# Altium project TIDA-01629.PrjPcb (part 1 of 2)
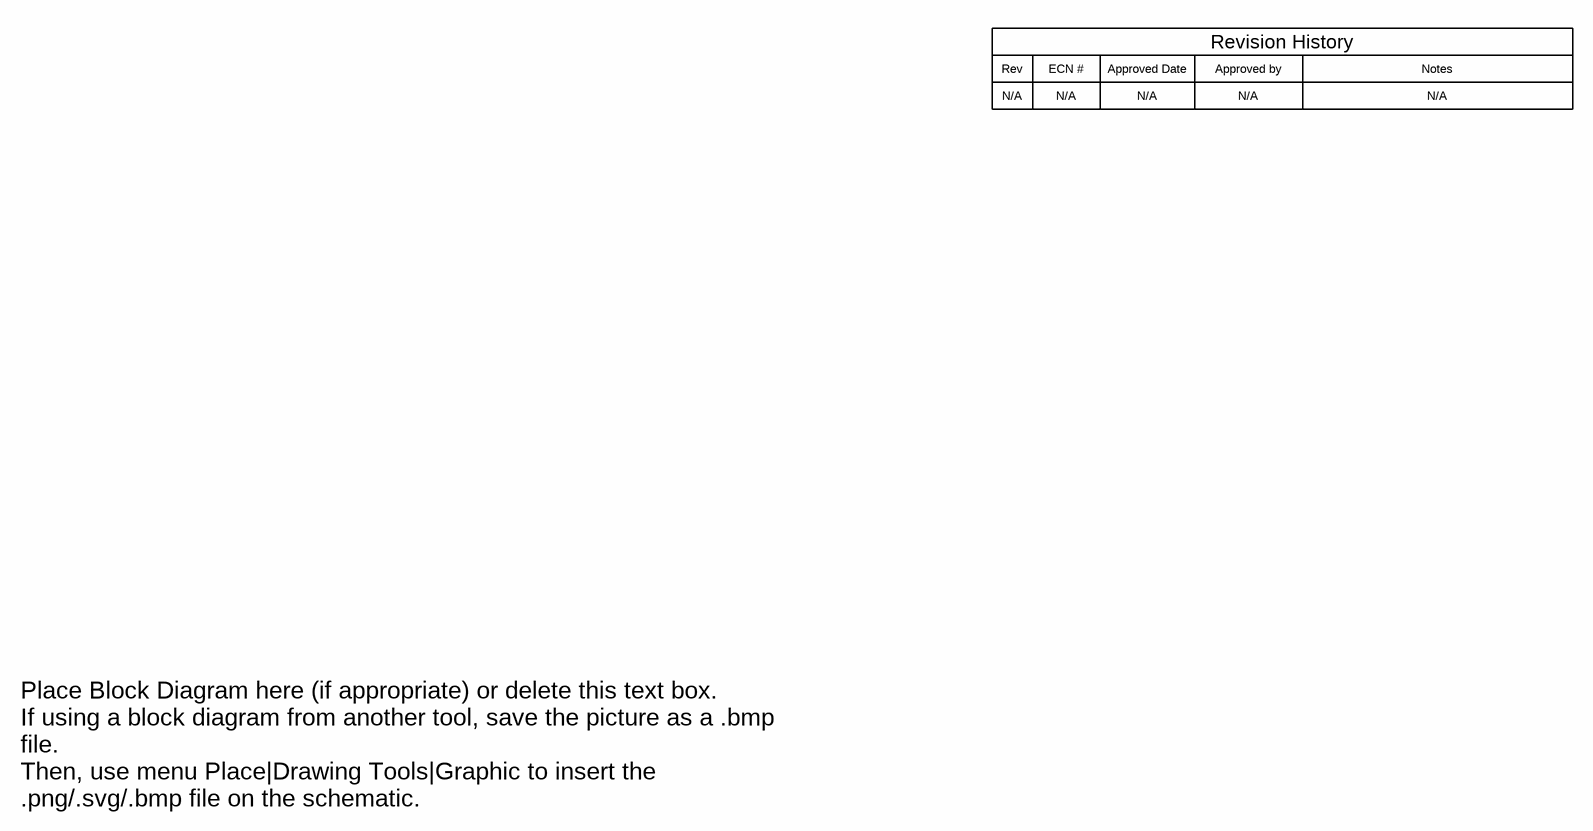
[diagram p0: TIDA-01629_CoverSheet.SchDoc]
TID: TIDA-01629; TechSupport: http://www.ti.com/support; SCH_Rev: E1; PRJ_Title: 48V/530W three phase inverter with smart gate driver; PRJ_Number: TIDA-01629; PRJ_Engineer: Kristen Mogensen; PRJ_Customer: Public Release; PCB_Rev: E1; PCB_Layout: Kristen Mogensen; ChangeMe!: N/A; CopyrightYear: 2018
6 sheets, 224 parts. Net scope: global (net labels, ports and power ports of the same name join across sheets).
Board file: TIDA-01629_PCB.PcbDoc
Sheets:
  TIDA-01629_CoverSheet.SchDoc
  TIDA-01629_CurrentSense.SchDoc
  TIDA-01629_EVM_Hardware.SchDoc
  TIDA-01629_Gate_Driver.SchDoc
  TIDA-01629_Interface.SchDoc
  TIDA-01629_Encoder.SchDoc

## Sheet TIDA-01629_CoverSheet.SchDoc
size 431 x 279 mm; Date: Not shown in title block; ApprovedBy: Not shown in title block; CheckedBy: Not shown in title block; Author: Not shown in title block; CompanyName: Not shown in title block; Engineer: Not shown in title block; Organization: Not shown in title block; Address1: Not shown in title block; Address2: Not shown in title block; Address3: Not shown in title block; Address4: Not shown in title block; DocumentNumber: 1; Revision: Use project parameter SCH_Rev; SheetNumber: 1; SheetTotal: 3; PageSetup: Record=PageOptions¦CenterHorizontal=True¦CenterVertical=True¦PrintScale=1.00¦XCorrection=1.00¦YCorrection=1.00¦PrintKind=0¦BorderSize=5000000¦LeftOffset=0¦BottomOffset=0¦Orientation=2¦PaperLength=1000¦PaperWidth=1000¦Scale=100¦PaperSource=15¦PrintQuality=600¦MediaType=1¦DitherType=10¦PaperKind=Letter¦PrintScaleMode=1

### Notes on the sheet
- Rev
- N/A
- ECN #
- Approved Date
- Approved by
- Revision History
- Notes
- Place Block Diagram here (if appropriate) or delete this text box.
  If using a block diagram from another tool, save the picture as a .bmp file.
  Then, use menu Place|Drawing Tools|Graphic to insert the .png/.svg/.bmp file on the schematic.

## Sheet TIDA-01629_CurrentSense.SchDoc
size 431 x 279 mm; Date: Not shown in title block; ApprovedBy: Not shown in title block; CheckedBy: Not shown in title block; Author: Not shown in title block; CompanyName: Not shown in title block; Engineer: Not shown in title block; Organization: Not shown in title block; Address1: Not shown in title block; Address2: Not shown in title block; Address3: Not shown in title block; Address4: Not shown in title block; DocumentNumber: 1; Revision: Use project parameter SCH_Rev; SheetNumber: 2; SheetTotal: 3; PageSetup: Record=PageOptions¦CenterHorizontal=True¦CenterVertical=True¦PrintScale=1.00¦XCorrection=1.00¦YCorrection=1.00¦PrintKind=0¦BorderSize=5000000¦LeftOffset=0¦BottomOffset=0¦Orientation=2¦PaperLength=1000¦PaperWidth=1000¦Scale=100¦PaperSource=15¦PrintQuality=600¦MediaType=1¦DitherType=10¦PaperKind=Letter¦PrintScaleMode=1
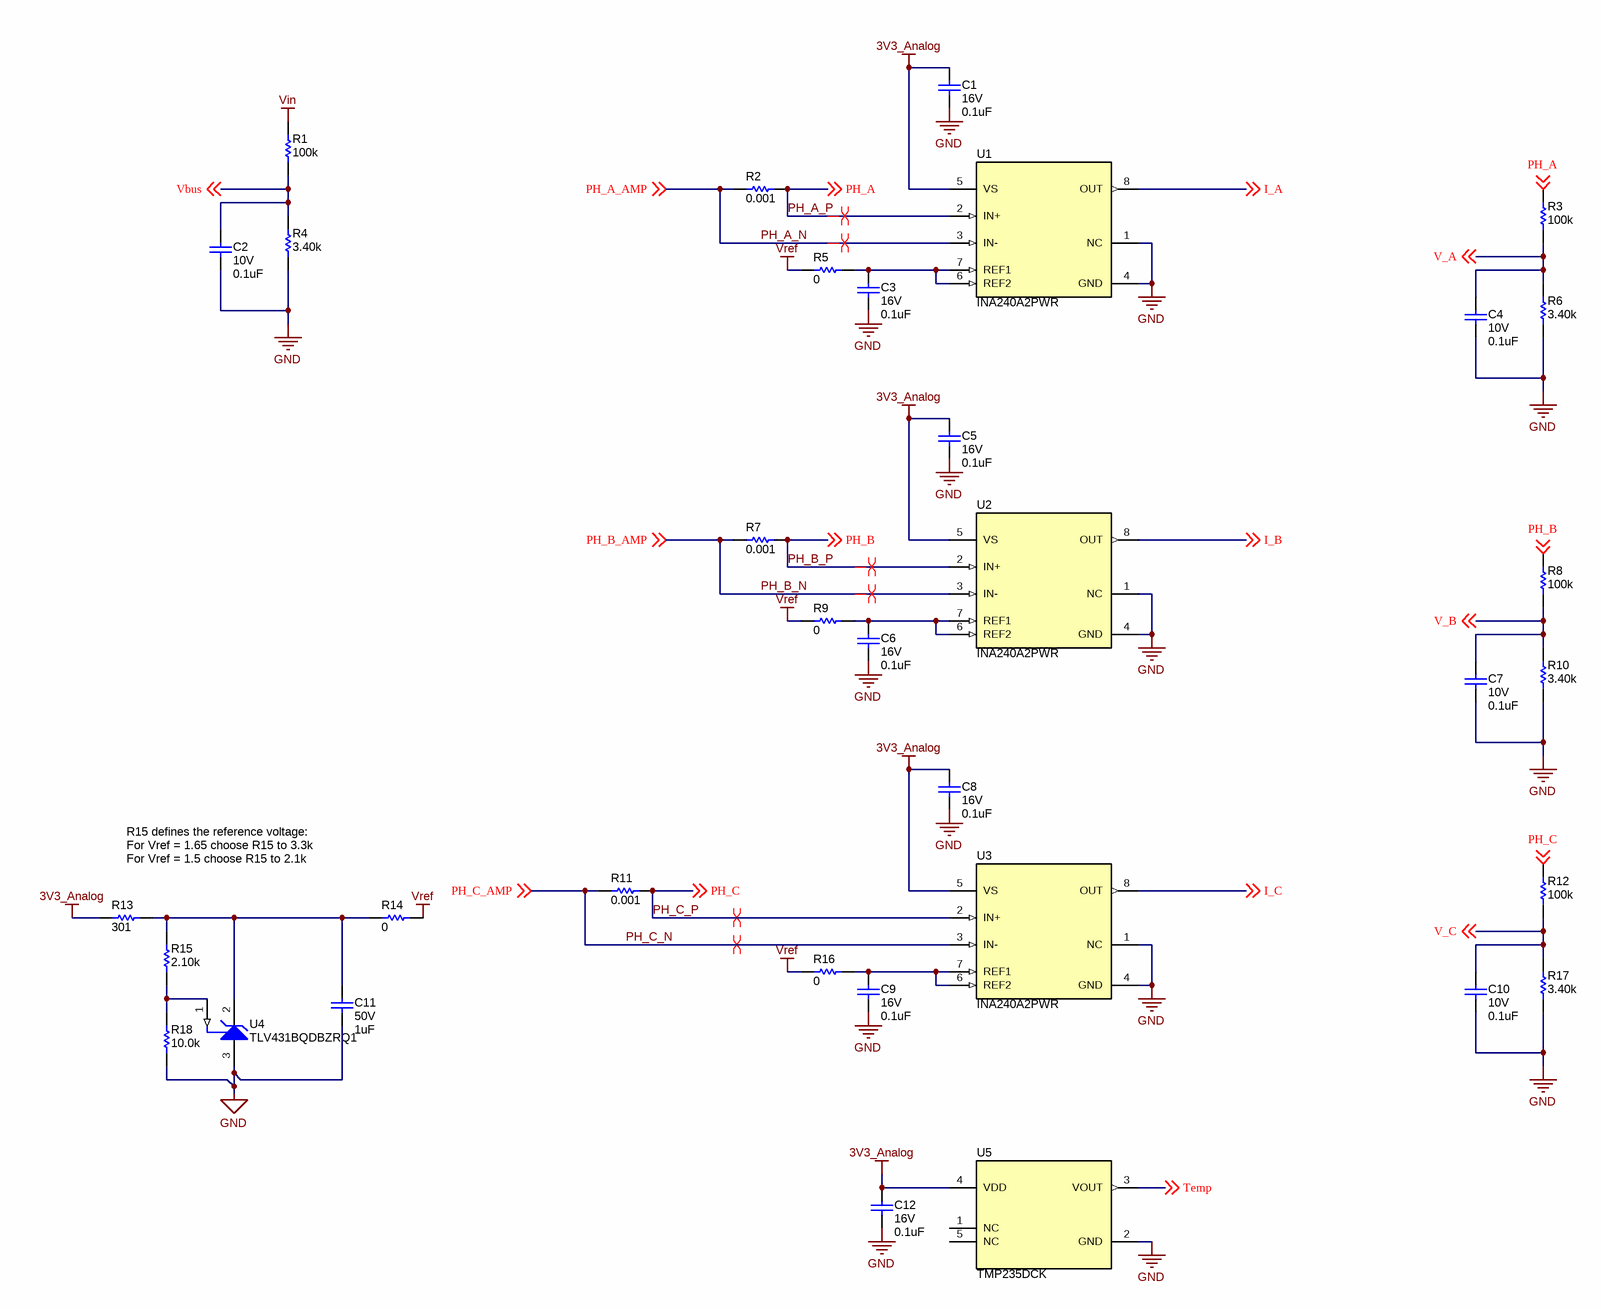
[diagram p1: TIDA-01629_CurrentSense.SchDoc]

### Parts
C1  VDC_V: 16V  ValueDisplayed: 0.1uF  [0402]  (hidden comment: 885012205037)
C2  VDC_V: 10V  ValueDisplayed: 0.1uF  [0402]  (hidden comment: GRM155R71A104KA01D)
C3  VDC_V: 16V  ValueDisplayed: 0.1uF  [0402]  (hidden comment: 885012205037)
C4  VDC_V: 10V  ValueDisplayed: 0.1uF  [0402]  (hidden comment: GRM155R71A104KA01D)
C5  VDC_V: 16V  ValueDisplayed: 0.1uF  [0402]  (hidden comment: 885012205037)
C6  VDC_V: 16V  ValueDisplayed: 0.1uF  [0402]  (hidden comment: 885012205037)
C7  VDC_V: 10V  ValueDisplayed: 0.1uF  [0402]  (hidden comment: GRM155R71A104KA01D)
C8  VDC_V: 16V  ValueDisplayed: 0.1uF  [0402]  (hidden comment: 885012205037)
C9  VDC_V: 16V  ValueDisplayed: 0.1uF  [0402]  (hidden comment: 885012205037)
C10  VDC_V: 10V  ValueDisplayed: 0.1uF  [0402]  (hidden comment: GRM155R71A104KA01D)
C11  VDC_V: 50V  ValueDisplayed: 1uF  [0805_HV]  (hidden comment: 885012207103)
C12  VDC_V: 16V  ValueDisplayed: 0.1uF  [0402]  (hidden comment: 885012205037)
R1  ValueDisplayed: 100k  [0402]  (hidden comment: CRCW0402100KFKED)
R2  ValueDisplayed: 0.001  [1206]  (hidden comment: CRF1206-FZ-R001ELF)
R3  ValueDisplayed: 100k  [0402]  (hidden comment: CRCW0402100KFKED)
R4  ValueDisplayed: 3.40k  [0402]  (hidden comment: CRCW04023K40FKED)
R5  ValueDisplayed: 0  [0402]  (hidden comment: CRCW04020000Z0ED)
R6  ValueDisplayed: 3.40k  [0402]  (hidden comment: CRCW04023K40FKED)
R7  ValueDisplayed: 0.001  [1206]  (hidden comment: CRF1206-FZ-R001ELF)
R8  ValueDisplayed: 100k  [0402]  (hidden comment: CRCW0402100KFKED)
R9  ValueDisplayed: 0  [0402]  (hidden comment: CRCW04020000Z0ED)
R10  ValueDisplayed: 3.40k  [0402]  (hidden comment: CRCW04023K40FKED)
R11  ValueDisplayed: 0.001  [1206]  (hidden comment: CRF1206-FZ-R001ELF)
R12  ValueDisplayed: 100k  [0402]  (hidden comment: CRCW0402100KFKED)
R13  ValueDisplayed: 301  [0603]  (hidden comment: CRCW0603301RFKEA)
R14  ValueDisplayed: 0  [0402]  (hidden comment: CRCW04020000Z0ED)
R15  ValueDisplayed: 2.10k  [0603]  (hidden comment: CRCW06032K10FKEA)
R16  ValueDisplayed: 0  [0402]  (hidden comment: CRCW04020000Z0ED)
R17  ValueDisplayed: 3.40k  [0402]  (hidden comment: CRCW04023K40FKED)
R18  ValueDisplayed: 10.0k  [0402]  (hidden comment: CRCW040210K0FKED)
U1  INA240A2PWR  [PW0008A_L]
U2  INA240A2PWR  [PW0008A_L]
U3  INA240A2PWR  [PW0008A_L]
U4  TLV431BQDBZRQ1  [DBZ0003A_N]
U5  TMP235DCK  [DCK0005A_N]

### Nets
3V3_Analog: C1.1 C5.1 C8.1 C12.1 R13.1 U1.5(VS) U2.5(VS) U3.5(VS) U5.4(VDD)
GND: C1.2 C2.2 C3.2 C4.2 C5.2 C6.2 C7.2 C8.2 C9.2 C10.2 C11.2 C12.2 R4.1 R6.1 R10.1 R17.1 R18.1 U1.1(NC) U1.4(GND) U2.1(NC) U2.4(GND) U3.1(NC) U3.4(GND) U4.3(ANODE) U5.2(GND)
Vin: R1.1
Vref: R5.2 R9.2 R14.1 R16.2
I_A: U1.8(OUT) ; off-sheet I_A
I_B: U2.8(OUT) ; off-sheet I_B
I_C: U3.8(OUT) ; off-sheet I_C
PH_A_N: R2.1 U1.3(IN-) ; off-sheet PH_A_AMP  [also labelled PH_A_AMP]
PH_A_P: R2.2 R3.1 U1.2(IN+) ; off-sheet PH_A  [also labelled PH_A]
PH_B_N: R7.1 U2.3(IN-) ; off-sheet PH_B_AMP  [also labelled PH_B_AMP]
PH_B_P: R7.2 R8.1 U2.2(IN+) ; off-sheet PH_B  [also labelled PH_B]
PH_C_N: R11.1 U3.3(IN-) ; off-sheet PH_C_AMP  [also labelled PH_C_AMP]
PH_C_P: R11.2 R12.1 U3.2(IN+) ; off-sheet PH_C  [also labelled PH_C]
Temp: U5.3(VOUT) ; off-sheet Temp
V_A: C4.1 R3.2 R6.2 ; off-sheet V_A
V_B: C7.1 R8.2 R10.2 ; off-sheet V_B
V_C: C10.1 R12.2 R17.2 ; off-sheet V_C
Vbus: C2.1 R1.2 R4.2 ; off-sheet Vbus
NetC3_1: C3.1 R5.1 U1.6(REF2) U1.7(REF1)
NetC6_1: C6.1 R9.1 U2.6(REF2) U2.7(REF1)
NetC9_1: C9.1 R16.1 U3.6(REF2) U3.7(REF1)
NetC11_1: C11.1 R13.2 R14.2 R15.2 U4.2(CATHODE)
NetR15_1: R15.1 R18.2 U4.1(REF)

Not connected (* = marked no-connect by the designer): U5 1(NC) 5(NC)

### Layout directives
differential pair: PH_A_N, PH_A_P, PH_B_N, PH_B_P, PH_C_N, PH_C_P

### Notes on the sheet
- R15 defines the reference voltage:
  For Vref = 1.65 choose R15 to 3.3k
  For Vref = 1.5 choose R15 to 2.1k

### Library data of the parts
C1 C3 C5 C6 C8 C9 C12 = CMP-0006228-2: CAP, CERM, 0.1 uF, 16 V, +/- 10%, X7R, 0402; Manufacturer: Wurth Elektronik; TaMin_C: -55°C; Polarized: N; SizeAreaWB_mm2: 3; Value1: Unknown; U/M: EA; Value: 0.1uF; TaMax_C: 125°C; SizeZ_mm: 0.6; SizeX_mm: 1; SizeY_mm: 0.5; Cap_F: 100nF; AEC Category: Q200
C2 C4 C7 C10 = CMP-0006629-2: CAP, CERM, 0.1 uF, 10 V, +/- 10%, X7R, 0402; Manufacturer: MuRata; TaMin_C: -55°C; Polarized: N; SizeAreaWB_mm2: 3; Value1: Unknown; U/M: EA; Value: 0.1uF; TaMax_C: 125°C; SizeZ_mm: 0.6; SizeX_mm: 1; SizeY_mm: 0.5; Cap_F: 100nF; AEC Category: Q200
C11 = CMP-0007696-2: CAP, CERM, 1 uF, 50 V, +/- 10%, X7R, 0805; Manufacturer: Wurth Elektronik; TaMin_C: -55°C; Polarized: N; SizeAreaWB_mm2: 6.75; Value1: Unknown; U/M: EA; Value: 1uF; TaMax_C: 125°C; SizeZ_mm: 1.45; SizeX_mm: 2; SizeY_mm: 1.25; Cap_Case: 0805; SizeArea_mm2: 2.5; Cap_F: 1µF; AEC Category: Q200
R1 R3 R8 R12 = CMP-0025950-3: RES, 100 k, 1%, 0.063 W, AEC-Q200 Grade 0, 0402; Manufacturer: Vishay-Dale; Power_W: 63mW; TempCo: 100 ppm/C; Value: 100k; EIA_Code: E96; SizeX_mm: 1; SizeY_mm: 0.5; SizeZ_mm: 0.6; Value2: 0.063W; AEC Qualified: Y; VDC_V: 50V; AEC Category: Q200; AEC Grade: 0
R2 R7 R11 = CMP-0078821-1: RES, 0.001, 1%, 1 W, AEC-Q200 Grade 0, 1206; Manufacturer: Bourns; Value_Code: 1L000; SizeArea_mm2: 5.12; AEC Qualified: Y; AEC Category: Q200; Res_ohm: 1m; Value: 0.001; SizeZ_mm: 1.35; EIA_Code: E96; TempCo: 50 ppm/C; AEC Grade: 0; SizeY_mm: 1.6; Power_W: 1W; SizeX_mm: 3.2
R4 R6 R10 R17 = CMP-0026334-2: RES, 3.40 k, 1%, 0.063 W, AEC-Q200 Grade 0, 0402; Manufacturer: Vishay-Dale; Power_W: 63mW; TempCo: 100 ppm/C; Value_Code: 3k40; Value: 3.40k; EIA_Code: E96; Res_ohm: 3.4k; SizeX_mm: 1; SizeY_mm: 0.5; SizeZ_mm: 0.6; Value2: 0.063W; AEC Qualified: Y; VDC_V: 50V; AEC Category: Q200; AEC Grade: 0
R5 R9 R14 R16 = CMP-0026822-2: RES, 0, 5%, 0.063 W, 0402; Manufacturer: Vishay-Dale; Power_W: 63mW; TempCo: 200 ppm/C; Value_Code: 0000; U/M: EA; Value: 0; EIA_Code: E24; SizeX_mm: 1; SizeY_mm: 0.5; SizeZ_mm: 0.6; Value2: 0.063W; VDC_V: 50V; AEC Category: Q200
R13 = CMP-0022321-5: RES, 301, 1%, 0.1 W, AEC-Q200 Grade 0, 0603; Manufacturer: Vishay-Dale; Power_W: 100mW; TempCo: 100 ppm/C; Value_Code: 301R; Value: 301; EIA_Code: E96; SizeX_mm: 1.6; SizeY_mm: 0.8; SizeZ_mm: 1; Value2: 0.1W; SizeArea_mm2: 1.28; AEC Qualified: Y; VDC_V: 75V; AEC Category: Q200; AEC Grade: 0
R15 = CMP-0022270-4: RES, 2.10 k, 1%, 0.1 W, AEC-Q200 Grade 0, 0603; Manufacturer: Vishay-Dale; Power_W: 100mW; TempCo: 100 ppm/C; Value_Code: 2k10; Value: 2.10k; EIA_Code: E96; Res_ohm: 2.1k; SizeX_mm: 1.6; SizeY_mm: 0.8; SizeZ_mm: 1; Value2: 0.1W; SizeArea_mm2: 1.28; AEC Qualified: Y; VDC_V: 75V; AEC Category: Q200; AEC Grade: 0
R18 = CMP-0025958-3: RES, 10.0 k, 1%, 0.063 W, AEC-Q200 Grade 0, 0402; Manufacturer: Vishay-Dale; Power_W: 63mW; TempCo: 100 ppm/C; Value_Code: 10k0; Value: 10.0k; EIA_Code: E96; Res_ohm: 10k; SizeX_mm: 1; SizeY_mm: 0.5; SizeZ_mm: 0.6; Value2: 0.063W; AEC Qualified: Y; VDC_V: 50V; AEC Category: Q200; AEC Grade: 0
U1-U3 = CMP-0075735-1: High/Low Side, Bi-Directional Zero-Drift Current Sense Amp w/ Enhanced PWM Rejection, PW0008A (TSSOP-8); Alternate Manufacturer: Texas Instruments; SizeX_mm: 6.4; CompType: IC; SizeAreaWB_mm2: 42.0; SizeZ_mm: 1.2; SizeY_mm: 3.0; U/M: EA; SizeArea_mm2: 19.2
U4 = CMP-0033032-1: Automotive Catalog Low-Voltage Adjustable Precision Shunt Regulator, 15 mA, -40 to 125 degC, 3-pin SOT-23 (DBZ), Green (RoHS & no Sb/Br); Manufacturer: Texas Instruments; VO Adj(Min)(V): 1.24; Iout/Iz(Max)(mA): 15; Min Iz for Regulation(uA): 80; Initial Accuracy @ 25/deg C(%): 0.5; VO Adj(Max)(V): 6; SubFamily: Shunt Voltage Reference
U5 = CMP-0013250-2: TMP235DCK, DCK0005A (SOT-5); Manufacturer: Texas Instruments; SizeX_mm: 2.1; SizeY_mm: 2; CompType: IC; SizeZ_mm: 1.1; SizeArea_mm2: 4.2; SizeAreaWB_mm2: 9.3; U/M: EA

## Sheet TIDA-01629_EVM_Hardware.SchDoc
size 431 x 279 mm; Date: Not shown in title block; ApprovedBy: Not shown in title block; CheckedBy: Not shown in title block; Author: Not shown in title block; CompanyName: Not shown in title block; Engineer: Not shown in title block; Organization: Not shown in title block; Address1: Not shown in title block; Address2: Not shown in title block; Address3: Not shown in title block; Address4: Not shown in title block; DocumentNumber: 1; Revision: Use project parameter SCH_Rev; SheetNumber: 3; SheetTotal: 3; PageSetup: Record=PageOptions¦CenterHorizontal=True¦CenterVertical=True¦PrintScale=1.00¦XCorrection=1.00¦YCorrection=1.00¦PrintKind=0¦BorderSize=5000000¦LeftOffset=0¦BottomOffset=0¦Orientation=2¦PaperLength=1000¦PaperWidth=1000¦Scale=100¦PaperSource=15¦PrintQuality=600¦MediaType=1¦DitherType=10¦PaperKind=Letter¦PrintScaleMode=1
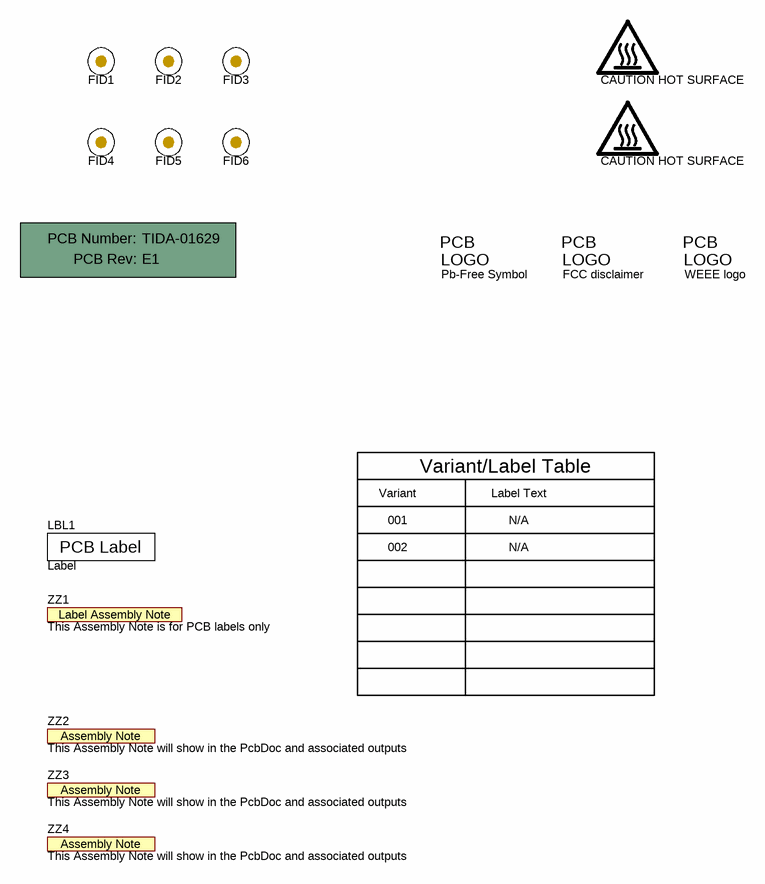
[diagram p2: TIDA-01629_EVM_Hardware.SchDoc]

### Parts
!PCB1  Printed Circuit Board  (value not drawn)  (mechanical)
FID1  Fiducial  [Fiducial10-20]  (value not drawn)
FID2  Fiducial  [Fiducial10-20]  (value not drawn)
FID3  Fiducial  [Fiducial10-20]  (value not drawn)
FID4  Fiducial  [Fiducial10-20]  (value not drawn)
FID5  Fiducial  [Fiducial10-20]  (value not drawn)
FID6  Fiducial  [Fiducial10-20]  (value not drawn)
LBL1  Label  [Label_650x200]
LOGO1  CAUTION HOT SURFACE  [IEC_HotSurface_Small]  (no BOM)
LOGO2  CAUTION HOT SURFACE  [IEC_HotSurface_Small]  (no BOM)
Logo4  Pb-Free Symbol  [Pb-Free_Overlay_Small]  (no BOM)
Logo5  FCC disclaimer  [FCC_disclaimer]  (no BOM)
Logo6  WEEE logo  [WEEE_Minimum]  (no BOM)
ZZ1  This Assembly Note is for PCB labels only  [AssemblyNoteLabel]  (no BOM)
ZZ2  This Assembly Note will show in the PcbDoc and associated outputs  [AssemblyNote]  (no BOM)
ZZ3  This Assembly Note will show in the PcbDoc and associated outputs  [AssemblyNote]  (no BOM)
ZZ4  This Assembly Note will show in the PcbDoc and associated outputs  [AssemblyNote]  (no BOM)

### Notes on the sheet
- Variant
- Variant/Label Table
- Label Text
- 001
- 002
- N/A

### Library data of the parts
!PCB1 = CMP-0003618-2: Manufacturer: Any; PartNumber: TIDA-01629
FID1-FID6 = CMP-0077181-1: Fiducial mark.  There is nothing to buy or mount.
LBL1 = CMP-0003625-1: Thermal Transfer Printable Labels, 0.650" W x 0.200" H - 10,000 per roll; Manufacturer: Brady; PartNumber: THT-14-423-10; Note: Size: 0.65" x 0.20 "
LOGO1 LOGO2 = CMP-0074837-1: IEC 61010-1 Hot Surface Warning; SymbolCreator: a0412235
Logo4 = CMP-0074839-1: SymbolCreator: a0412235; Library Reference: Logo
Logo5 = CMP-0074847-1: FCC_disclaimer; Library Reference: Logo
Logo6 = CMP-0074769-1
ZZ1 = CMP-0003616-3
ZZ2-ZZ4 = AssemblyNote: SymbolCreator: codlsc

## Sheet TIDA-01629_Gate_Driver.SchDoc
size 431 x 279 mm; Date: Not shown in title block; ApprovedBy: Not shown in title block; CheckedBy: Not shown in title block; Author: Not shown in title block; CompanyName: Not shown in title block; Engineer: Not shown in title block; Organization: Not shown in title block; Address1: Not shown in title block; Address2: Not shown in title block; Address3: Not shown in title block; Address4: Not shown in title block; DocumentNumber: 1; Revision: Use project parameter SCH_Rev; SheetNumber: 2; SheetTotal: 3; PageSetup: Record=PageOptions¦CenterHorizontal=True¦CenterVertical=True¦PrintScale=1.00¦XCorrection=1.00¦YCorrection=1.00¦PrintKind=0¦BorderSize=5000000¦LeftOffset=0¦BottomOffset=0¦Orientation=2¦PaperLength=1000¦PaperWidth=1000¦Scale=100¦PaperSource=15¦PrintQuality=600¦MediaType=1¦DitherType=10¦PaperKind=Letter¦PrintScaleMode=1
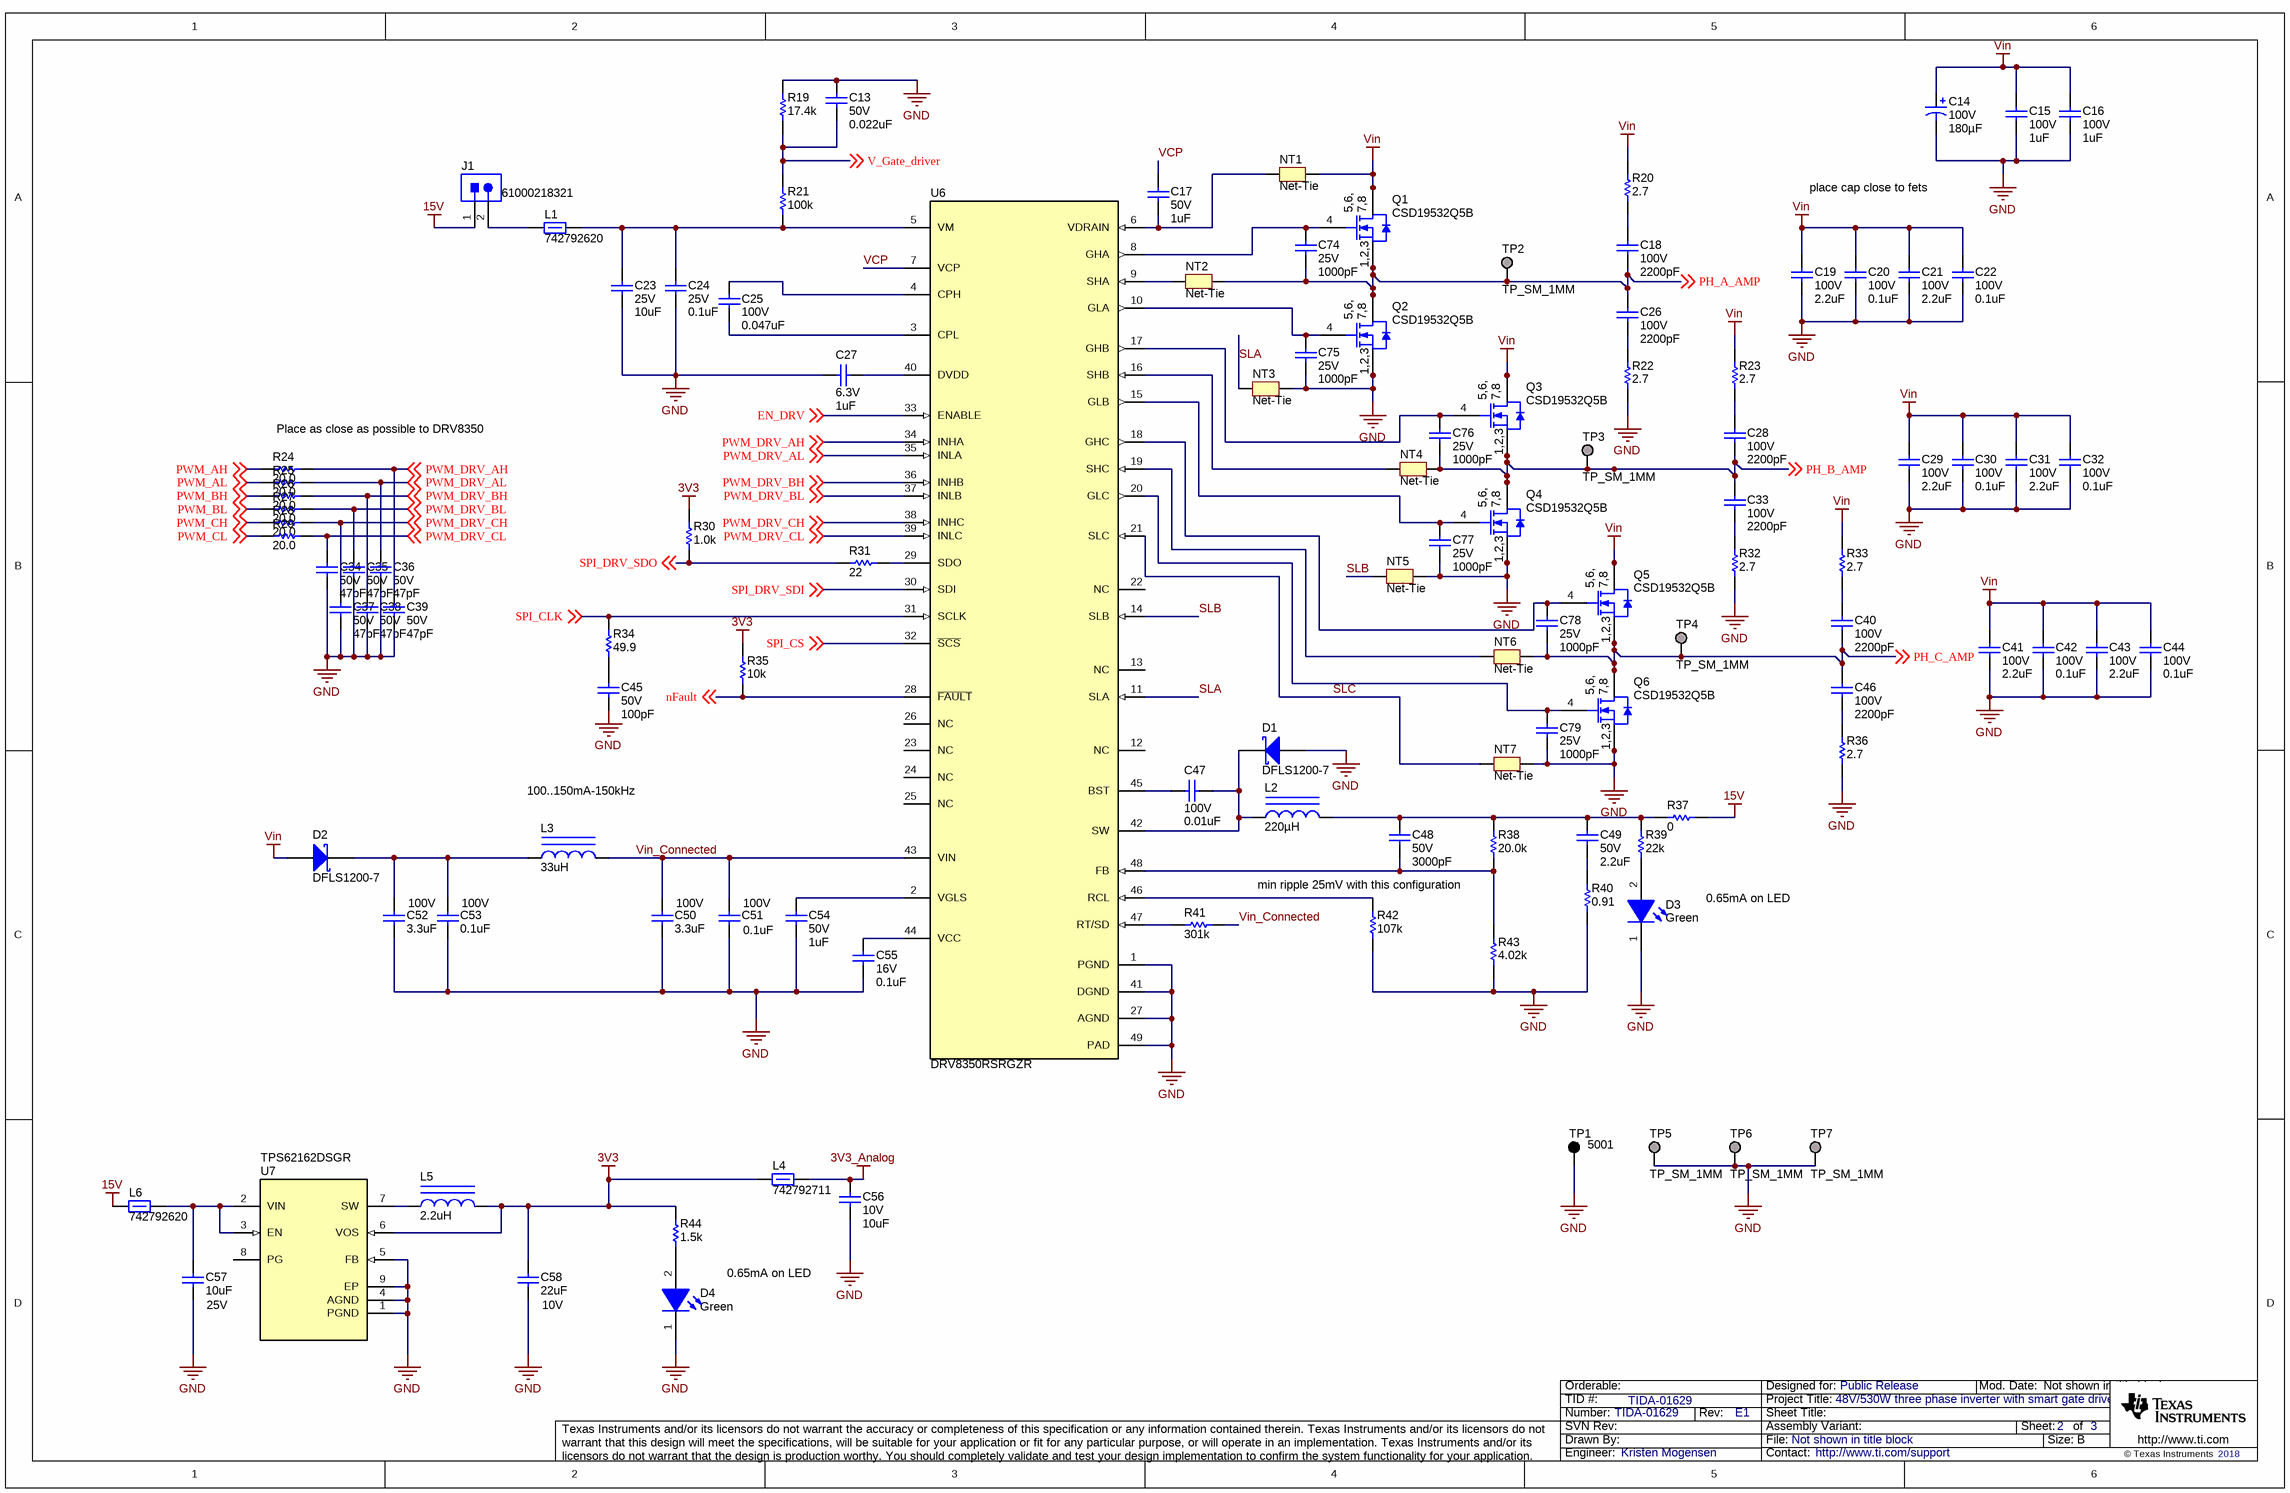
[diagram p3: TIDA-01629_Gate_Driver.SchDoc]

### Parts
C13  VDC_V: 50V  ValueDisplayed: 0.022uF  [0402]  (hidden comment: GCM155R71H223KA55D)
C14  VDC_V: 100V  ValueDisplayed: 180µF  [KYB_1250x2000]  (hidden comment: EKYB101ELL181MK20S)
C15  VDC_V: 100V  ValueDisplayed: 1uF  [1210_270]  (hidden comment: GRM32ER72A105KA01L)
C16  VDC_V: 100V  ValueDisplayed: 1uF  [1210_270]  (hidden comment: GRM32ER72A105KA01L)
C17  VDC_V: 50V  ValueDisplayed: 1uF  [0603]  (hidden comment: GRM188R61H105KAALD)
C18  VDC_V: 100V  ValueDisplayed: 2200pF  [0603L]  (hidden comment: GRM188R72A222KA01D)
C19  VDC_V: 100V  ValueDisplayed: 2.2uF  [1210_270]  (hidden comment: GRM32ER72A225KA35L)
C20  VDC_V: 100V  ValueDisplayed: 0.1uF  [0603]  (hidden comment: GRM188R72A104KA35J)
C21  VDC_V: 100V  ValueDisplayed: 2.2uF  [1210_270]  (hidden comment: GRM32ER72A225KA35L)
C22  VDC_V: 100V  ValueDisplayed: 0.1uF  [0603]  (hidden comment: GRM188R72A104KA35J)
C23  VDC_V: 25V  ValueDisplayed: 10uF  [0805_HV]  (hidden comment: GRM21BZ71E106KE15L)
C24  VDC_V: 25V  ValueDisplayed: 0.1uF  [0402]  (hidden comment: GRM155R71E104KE14D)
C25  VDC_V: 100V  ValueDisplayed: 0.047uF  [0805_HV]  (hidden comment: GRM21BR72A473KA01L)
C26  VDC_V: 100V  ValueDisplayed: 2200pF  [0603L]  (hidden comment: GRM188R72A222KA01D)
C27  VDC_V: 6.3V  ValueDisplayed: 1uF  [0402]  (hidden comment: GRM155R70J105MA12D)
C28  VDC_V: 100V  ValueDisplayed: 2200pF  [0603L]  (hidden comment: GRM188R72A222KA01D)
C29  VDC_V: 100V  ValueDisplayed: 2.2uF  [1210_270]  (hidden comment: GRM32ER72A225KA35L)
C30  VDC_V: 100V  ValueDisplayed: 0.1uF  [0603]  (hidden comment: GRM188R72A104KA35J)
C31  VDC_V: 100V  ValueDisplayed: 2.2uF  [1210_270]  (hidden comment: GRM32ER72A225KA35L)
C32  VDC_V: 100V  ValueDisplayed: 0.1uF  [0603]  (hidden comment: GRM188R72A104KA35J)
C33  VDC_V: 100V  ValueDisplayed: 2200pF  [0603L]  (hidden comment: GRM188R72A222KA01D)
C34  VDC_V: 50V  ValueDisplayed: 47pF  [0402L]  (hidden comment: 885012005044)
C35  VDC_V: 50V  ValueDisplayed: 47pF  [0402L]  (hidden comment: 885012005044)
C36  VDC_V: 50V  ValueDisplayed: 47pF  [0402L]  (hidden comment: 885012005044)
C37  VDC_V: 50V  ValueDisplayed: 47pF  [0402L]  (hidden comment: 885012005044)
C38  VDC_V: 50V  ValueDisplayed: 47pF  [0402L]  (hidden comment: 885012005044)
C39  VDC_V: 50V  ValueDisplayed: 47pF  [0402L]  (hidden comment: 885012005044)
C40  VDC_V: 100V  ValueDisplayed: 2200pF  [0603L]  (hidden comment: GRM188R72A222KA01D)
C41  VDC_V: 100V  ValueDisplayed: 2.2uF  [1210_270]  (hidden comment: GRM32ER72A225KA35L)
C42  VDC_V: 100V  ValueDisplayed: 0.1uF  [0603]  (hidden comment: GRM188R72A104KA35J)
C43  VDC_V: 100V  ValueDisplayed: 2.2uF  [1210_270]  (hidden comment: GRM32ER72A225KA35L)
C44  VDC_V: 100V  ValueDisplayed: 0.1uF  [0603]  (hidden comment: GRM188R72A104KA35J)
C45  VDC_V: 50V  ValueDisplayed: 100pF  [0402]  (hidden comment: 885012005061)
C46  VDC_V: 100V  ValueDisplayed: 2200pF  [0603L]  (hidden comment: GRM188R72A222KA01D)
C47  VDC_V: 100V  ValueDisplayed: 0.01uF  [0603]  (hidden comment: GRM188R72A103KA01D)
C48  VDC_V: 50V  ValueDisplayed: 3000pF  [0603]  (hidden comment: GRM1885C1H302JA01D)
C49  VDC_V: 50V  ValueDisplayed: 2.2uF  [0805_HV]  (hidden comment: C2012X7R1H225K125AC)
C50  ValueDisplayed: 3.3uF  Value2: 100V  [1206_190]  (hidden comment: Capacitor)
C51  VDC_V: 100V  ValueDisplayed: 0.1uF  [0603]  (hidden comment: GRM188R72A104KA35J)
C52  ValueDisplayed: 3.3uF  Value2: 100V  [1206_190]  (hidden comment: Capacitor)
C53  ValueDisplayed: 0.1uF  Value2: 100V  [0603]  (hidden comment: Capacitor)
C54  VDC_V: 50V  ValueDisplayed: 1uF  [0603]  (hidden comment: UMK107AB7105KA-T)
C55  VDC_V: 16V  ValueDisplayed: 0.1uF  [0402]  (hidden comment: 885012205037)
C56  VDC_V: 10V  ValueDisplayed: 10uF  [0805_HV]  (hidden comment: 885012207026)
C57  ValueDisplayed: 10uF  Value2: 25V  [0603S]  (hidden comment: Capacitor)
C58  ValueDisplayed: 22uF  Value2: 10V  [0603S]  (hidden comment: Capacitor)
C74  VDC_V: 25V  ValueDisplayed: 1000pF  [0603]  (hidden comment: GRM1885C1E102JA01D)
C75  VDC_V: 25V  ValueDisplayed: 1000pF  [0603]  (hidden comment: GRM1885C1E102JA01D)
C76  VDC_V: 25V  ValueDisplayed: 1000pF  [0603]  (hidden comment: GRM1885C1E102JA01D)
C77  VDC_V: 25V  ValueDisplayed: 1000pF  [0603]  (hidden comment: GRM1885C1E102JA01D)
C78  VDC_V: 25V  ValueDisplayed: 1000pF  [0603]  (hidden comment: GRM1885C1E102JA01D)
C79  VDC_V: 25V  ValueDisplayed: 1000pF  [0603]  (hidden comment: GRM1885C1E102JA01D)
D1  DFLS1200-7  [PowerDI123]
D2  DFLS1200-7  [PowerDI123]
D3  value Green  [WL-SMCW_GREEN]  (hidden comment: LED_A2_K1)
D4  value Green  [WL-SMCW_GREEN]  (hidden comment: LED_A2_K1)
J1  61000218321  [Wurth_61000218321]
L1  742792620  [0603]
L2  ValueDisplayed: 220µH  [MSS7348]  (hidden comment: MSS7348-224MEB)
L3  ValueDisplayed: 33uH  [NLCV25]  (hidden comment: Inductor_Iron)
L4  742792711  [0402]
L5  ValueDisplayed: 2.2uH  [XFL3012]  (hidden comment: Inductor_Iron)
L6  742792620  [0603]
NT1  Net-Tie  [Net-Tie_10milWide_30milLong]  (net tie, no BOM)
NT2  Net-Tie  [Net-Tie_10milWide_30milLong]  (net tie, no BOM)
NT3  Net-Tie  [Net-Tie_10milWide_30milLong]  (net tie, no BOM)
NT4  Net-Tie  [Net-Tie_10milWide_30milLong]  (net tie, no BOM)
NT5  Net-Tie  [Net-Tie_10milWide_30milLong]  (net tie, no BOM)
NT6  Net-Tie  [Net-Tie_10milWide_30milLong]  (net tie, no BOM)
NT7  Net-Tie  [Net-Tie_10milWide_30milLong]  (net tie, no BOM)
Q1  CSD19532Q5B  [DNK0008A]
Q2  CSD19532Q5B  [DNK0008A]
Q3  CSD19532Q5B  [DNK0008A]
Q4  CSD19532Q5B  [DNK0008A]
Q5  CSD19532Q5B  [DNK0008A]
Q6  CSD19532Q5B  [DNK0008A]
R19  ValueDisplayed: 17.4k  [0402]  (hidden comment: CRCW040217K4FKED)
R20  ValueDisplayed: 2.7  [0805L]  (hidden comment: CRCW08052R70JNEA)
R21  ValueDisplayed: 100k  [0402]  (hidden comment: CRCW0402100KFKED)
R22  ValueDisplayed: 2.7  [0805L]  (hidden comment: CRCW08052R70JNEA)
R23  ValueDisplayed: 2.7  [0805L]  (hidden comment: CRCW08052R70JNEA)
R24  ValueDisplayed: 20.0  [0402L]  (hidden comment: CRCW040220R0FKED)
R25  ValueDisplayed: 20.0  [0402L]  (hidden comment: CRCW040220R0FKED)
R26  ValueDisplayed: 20.0  [0402L]  (hidden comment: CRCW040220R0FKED)
R27  ValueDisplayed: 20.0  [0402L]  (hidden comment: CRCW040220R0FKED)
R28  ValueDisplayed: 20.0  [0402L]  (hidden comment: CRCW040220R0FKED)
R29  ValueDisplayed: 20.0  [0402L]  (hidden comment: CRCW040220R0FKED)
R30  ValueDisplayed: 1.0k  [0402]  (hidden comment: CRCW04021K00JNED)
R31  ValueDisplayed: 22  [0402]  (hidden comment: CRCW040222R0JNED)
R32  ValueDisplayed: 2.7  [0805L]  (hidden comment: CRCW08052R70JNEA)
R33  ValueDisplayed: 2.7  [0805L]  (hidden comment: CRCW08052R70JNEA)
R34  ValueDisplayed: 49.9  [0402]  (hidden comment: CRCW040249R9FKED)
R35  ValueDisplayed: 10k  [0402]  (hidden comment: CRCW040210K0JNED)
R36  ValueDisplayed: 2.7  [0805L]  (hidden comment: CRCW08052R70JNEA)
R37  ValueDisplayed: 0  [0805_HV]  (hidden comment: CRCW08050000Z0EA)
R38  ValueDisplayed: 20.0k  [0402]  (hidden comment: CRCW040220K0FKED)
R39  ValueDisplayed: 22k  [0402]  (hidden comment: CRCW040222K0JNED)
R40  ValueDisplayed: 0.91  [0402]  (hidden comment: ERJ-2BQFR91X)
R41  ValueDisplayed: 301k  [0402S]  (hidden comment: CRCW0402301KFKED)
R42  ValueDisplayed: 107k  [0402]  (hidden comment: CRCW0402107KFKED)
R43  ValueDisplayed: 4.02k  [0402]  (hidden comment: CRCW04024K02FKED)
R44  ValueDisplayed: 1.5k  [0402]  (hidden comment: CRCW04021K50JNED)
TP1  5001  [Keystone5001]
TP2  TP_SM_1MM  [TP_SM_1MM]  (no BOM)
TP3  TP_SM_1MM  [TP_SM_1MM]  (no BOM)
TP4  TP_SM_1MM  [TP_SM_1MM]  (no BOM)
TP5  TP_SM_1MM  [TP_SM_1MM]  (no BOM)
TP6  TP_SM_1MM  [TP_SM_1MM]  (no BOM)
TP7  TP_SM_1MM  [TP_SM_1MM]  (no BOM)
U6  DRV8350RSRGZR  [RGZ0048L]
U7  PartNumber: TPS62162DSGR  [DSG0008A]  (hidden comment: TI-TPS62162DSG8-1600X900TP)

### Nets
3V3: C58.1 L4.1 L5.2 R30.2 R35.2 R44.2 U7.6(VOS)
3V3_Analog: C56.1 L4.2
15V: J1.1 L6.1 R37.2
GND: C13.1 C14.2(-) C15.2 C16.2 C19.2 C20.2 C21.2 C22.2 C23.2 C24.2 C27.2 C29.2 C30.2 C31.2 C32.2 C34.2 C35.2 C36.2 C37.2 C38.2 C39.2 C41.2 C42.2 C43.2 C44.2 C45.2 C50.2 C51.2 C52.2 C53.2 C54.2 C55.2 C56.2 C57.2 C58.2 C75.2 C77.2 C79.2 D1.2(A) D3.1(K) D4.1(K) NT3.2 NT5.2 NT7.2 Q2.1(S) Q2.2(S) Q2.3(S) Q4.1(S) Q4.2(S) Q4.3(S) Q6.1(S) Q6.2(S) Q6.3(S) R19.2 R22.1 R32.1 R36.1 R40.1 R42.1 R43.1 TP1.1 TP5.1 TP6.1 TP7.1 U6.1(PGND) U6.27(AGND) U6.41(DGND) U6.49(PAD) U7.1(PGND) U7.4(AGND) U7.5(FB) U7.9(EP)
Vin: C14.1(+) C15.1 C16.1 C19.1 C20.1 C21.1 C22.1 C29.1 C30.1 C31.1 C32.1 C41.1 C42.1 C43.1 C44.1 D2.2(A) NT1.2 Q1.5(D) Q1.6(D) Q1.7(D) Q1.8(D) Q1.9(D) Q3.5(D) Q3.6(D) Q3.7(D) Q3.8(D) Q3.9(D) Q5.5(D) Q5.6(D) Q5.7(D) Q5.8(D) Q5.9(D) R20.2 R23.2 R33.2
EN_DRV: U6.33(ENABLE) ; off-sheet EN_DRV
nFault: R35.1 U6.28(~{FAULT}) ; off-sheet nFault
PH_A_AMP: C18.2 C26.1 C74.2 NT2.2 Q1.1(S) Q1.2(S) Q1.3(S) Q2.5(D) Q2.6(D) Q2.7(D) Q2.8(D) Q2.9(D) TP2.1 ; off-sheet PH_A_AMP  [project net PH_A_N]
PH_B_AMP: C28.2 C33.1 C76.2 NT4.2 Q3.1(S) Q3.2(S) Q3.3(S) Q4.5(D) Q4.6(D) Q4.7(D) Q4.8(D) Q4.9(D) TP3.1 ; off-sheet PH_B_AMP  [project net PH_B_N]
PH_C_AMP: C40.2 C46.1 C78.2 NT6.2 Q5.1(S) Q5.2(S) Q5.3(S) Q6.5(D) Q6.6(D) Q6.7(D) Q6.8(D) Q6.9(D) TP4.1 ; off-sheet PH_C_AMP  [project net PH_C_N]
PWM_AH: R24.1 ; off-sheet PWM_AH
PWM_AL: R25.1 ; off-sheet PWM_AL
PWM_BH: R26.1 ; off-sheet PWM_BH
PWM_BL: R27.1 ; off-sheet PWM_BL
PWM_CH: R28.1 ; off-sheet PWM_CH
PWM_CL: R29.1 ; off-sheet PWM_CL
PWM_DRV_AH: C39.1 R24.2 U6.34(INHA) ; off-sheet PWM_DRV_AH
PWM_DRV_AL: C36.1 R25.2 U6.35(INLA) ; off-sheet PWM_DRV_AL
PWM_DRV_BH: C38.1 R26.2 U6.36(INHB) ; off-sheet PWM_DRV_BH
PWM_DRV_BL: C35.1 R27.2 U6.37(INLB) ; off-sheet PWM_DRV_BL
PWM_DRV_CH: C37.1 R28.2 U6.38(INHC) ; off-sheet PWM_DRV_CH
PWM_DRV_CL: C34.1 R29.2 U6.39(INLC) ; off-sheet PWM_DRV_CL
SLA: NT3.1 U6.11(SLA)
SLB: NT5.1 U6.14(SLB)
SLC: NT7.1 U6.21(SLC)
SPI_CLK: R34.2 U6.31(SCLK) ; off-sheet SPI_CLK
SPI_CS: U6.32(~{SCS}) ; off-sheet SPI_CS
SPI_DRV_SDI: U6.30(SDI) ; off-sheet SPI_DRV_SDI
SPI_DRV_SDO: R30.1 R31.1 ; off-sheet SPI_DRV_SDO
V_Gate_driver: C13.2 R19.1 R21.2 ; off-sheet V_Gate_driver
VCP: C17.1 U6.7(VCP)
Vin_Connected: C50.1 C51.1 L3.2 R41.2 U6.43(VIN)
NetC17_2: C17.2 NT1.1 U6.6(VDRAIN)
NetC18_1: C18.1 R20.1
NetC23_1: C23.1 C24.1 L1.2 R21.1 U6.5(VM)
NetC25_1: C25.1 U6.4(CPH)
NetC25_2: C25.2 U6.3(CPL)
NetC26_2: C26.2 R22.2
NetC27_1: C27.1 U6.40(DVDD)
NetC28_1: C28.1 R23.1
NetC33_2: C33.2 R32.2
NetC40_1: C40.1 R33.1
NetC45_1: C45.1 R34.1
NetC46_2: C46.2 R36.2
NetC47_1: C47.1 D1.1(K) L2.1 U6.42(SW)
NetC47_2: C47.2 U6.45(BST)
NetC48_1: C48.1 C49.1 L2.2 R37.1 R38.2 R39.2
NetC48_2: C48.2 R38.1 R43.2 U6.48(FB)
NetC49_2: C49.2 R40.2
NetC52_1: C52.1 C53.1 D2.1(K) L3.1
NetC54_1: C54.1 U6.2(VGLS)
NetC55_1: C55.1 U6.44(VCC)
NetC57_1: C57.1 L6.2 U7.2(VIN) U7.3(EN)
NetC74_1: C74.1 Q1.4(G) U6.8(GHA)
NetC75_1: C75.1 Q2.4(G) U6.10(GLA)
NetC76_1: C76.1 Q3.4(G) U6.17(GHB)
NetC77_1: C77.1 Q4.4(G) U6.15(GLB)
NetC78_1: C78.1 Q5.4(G) U6.18(GHC)
NetC79_1: C79.1 Q6.4(G) U6.20(GLC)
NetD3_2: D3.2(A) R39.1
NetD4_2: D4.2(A) R44.1
NetJ1_2: J1.2 L1.1
NetL5_1: L5.1 U7.7(SW)
NetNT2_1: NT2.1 U6.9(SHA)
NetNT4_1: NT4.1 U6.16(SHB)
NetNT6_1: NT6.1 U6.19(SHC)
NetR31_2: R31.2 U6.29(SDO)
NetR41_1: R41.1 U6.47(RT/SD)
NetR42_2: R42.2 U6.46(RCL)

Not connected (* = marked no-connect by the designer): U6 12(NC) 13(NC) 22(NC) 23(NC) 24(NC) 25(NC) 26(NC); U7 8(PG)

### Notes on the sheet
- place cap close to fets
- Place as close as possible to DRV8350
- 100..150mA-150kHz
- min ripple 25mV with this configuration
- 0.65mA on LED

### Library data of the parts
C13 = CMP-0006358-2: CAP, CERM, 0.022 uF, 50 V, +/- 10%, C0G/NP0, 0402; Manufacturer: MuRata; TaMin_C: -55°C; Polarized: N; SizeAreaWB_mm2: 3; Value1: Unknown; U/M: EA; TaMax_C: 125°C; SizeZ_mm: 0.6; SizeX_mm: 1; SizeY_mm: 0.5; Cap_F: 22nF; AEC Category: Q200
C14 = CMP-0079802-1: CAP, AL, 180 µF, 100 V, +/- 20%, TH; Manufacturer: Chemi-Con; IRMS_A: 2.67dA; SizeAreaWB_mm2: 210.25; SizeArea_mm2: 156.25; AEC Qualified: N; AEC Category: Q200; Value: 180uF; TaMax_C: 105°C; SizeZ_mm: 21.5; Polarized: Y; TaMin_C: -40°C; SizeY_mm: 12.5; U/M: EA; CompType: Capacitor; Cap_Case: 12.5x20mm
C15 C16 = CMP-0009231-2: CAP, CERM, 1 uF, 100 V, +/- 10%, X7R, 1210; Manufacturer: MuRata; TaMin_C: -55°C; Polarized: N; SizeAreaWB_mm2: 14.7; Value1: Unknown; U/M: EA; Value: 1uF; TaMax_C: 125°C; SizeZ_mm: 2.7; SizeX_mm: 3.2; SizeY_mm: 2.5; Cap_Case: 1210; SizeArea_mm2: 8; Cap_F: 1µF; AEC Category: Q200
C17 = CMP-0007350-5: CAP, CERM, 1 uF, 50 V, +/- 10%, X5R, 0603; Manufacturer: MuRata; TaMin_C: -55°C; Polarized: N; SizeAreaWB_mm2: 4.68; Value1: Unknown; U/M: EA; Value: 1uF; TaMax_C: 85°C; SizeZ_mm: 1; SizeX_mm: 1.6; SizeY_mm: 0.8; SizeArea_mm2: 1.28; Cap_F: 1µF; AEC Category: Q200
C18 C26 C28 C33 C40 C46 = CMP-0007475-4: CAP, CERM, 2200 pF, 100 V, +/- 10%, X7R, 0603; Manufacturer: MuRata; TaMin_C: -55°C; Polarized: N; SizeAreaWB_mm2: 4.68; Value1: Unknown; U/M: EA; Value: 2200pF; TaMax_C: 125°C; SizeZ_mm: 1; SizeX_mm: 1.6; SizeY_mm: 0.8; Cap_Case: 0603; SizeArea_mm2: 1.28; CompType: Capacitor; Cap_F: 2.2nF; AEC Category: Q200
C19 C21 C29 C31 C41 C43 = CMP-0009232-2: CAP, CERM, 2.2 uF, 100 V, +/- 10%, X7R, 1210; Manufacturer: MuRata; TaMin_C: -55°C; ESR_ohm: 7m; Polarized: N; SizeAreaWB_mm2: 14.7; Value1: 0.007 ohm; U/M: EA; Value: 2.2uF; TaMax_C: 125°C; SizeZ_mm: 2.7; SizeX_mm: 3.2; SizeY_mm: 2.5; Cap_Case: 1210; SizeArea_mm2: 8; Cap_F: 2.2µF; IRMS_A: 4.4A; AEC Category: Q200
C20 C22 C30 C32 C42 C44 C51 = CMP-0007470-5: CAP, CERM, 0.1 uF, 100 V, +/- 10%, X7R, 0603; Manufacturer: MuRata; TaMin_C: -55°C; Polarized: N; SizeAreaWB_mm2: 4.68; Value1: Unknown; U/M: EA; Value: 0.1uF; TaMax_C: 125°C; SizeZ_mm: 1; SizeX_mm: 1.6; SizeY_mm: 0.8; SizeArea_mm2: 1.28; Cap_F: 100nF; AEC Category: Q200
C23 = CMP-0008378-2: CAP, CERM, 10 uF, 25 V, +/- 10%, X7R, 0805; Manufacturer: MuRata; TaMin_C: -55°C; Polarized: N; SizeAreaWB_mm2: 6.75; Value1: Unknown; U/M: EA; Value: 10uF; TaMax_C: 125°C; SizeZ_mm: 1.45; SizeX_mm: 2; SizeY_mm: 1.25; Cap_Case: 0805; SizeArea_mm2: 2.5; Cap_F: 10µF; AEC Category: Q200
C24 = CMP-0006659-2: CAP, CERM, 0.1 uF, 25 V, +/- 10%, X7R, 0402; Manufacturer: MuRata; TaMin_C: -55°C; Polarized: N; SizeAreaWB_mm2: 3; Value1: Unknown; U/M: EA; Value: 0.1uF; TaMax_C: 125°C; SizeZ_mm: 0.6; SizeX_mm: 1; SizeY_mm: 0.5; Cap_F: 100nF; AEC Category: Q200
C25 = CMP-0008373-2: CAP, CERM, 0.047 uF, 100 V, +/- 10%, X7R, 0805; Manufacturer: MuRata; TaMin_C: -55°C; Polarized: N; SizeAreaWB_mm2: 6.75; Value1: Unknown; U/M: EA; TaMax_C: 125°C; SizeZ_mm: 1.45; SizeX_mm: 2; SizeY_mm: 1.25; Cap_Case: 0805; SizeArea_mm2: 2.5; Cap_F: 47nF; AEC Category: Q200
C27 = CMP-0006624-2: CAP, CERM, 1 uF, 6.3 V, +/- 20%, X7R, 0402; Manufacturer: MuRata; TaMin_C: -55°C; Polarized: N; SizeAreaWB_mm2: 3; Value1: Unknown; U/M: EA; Value: 1uF; TaMax_C: 125°C; SizeZ_mm: 0.6; SizeX_mm: 1; SizeY_mm: 0.5; Cap_F: 1µF; AEC Category: Q200
C34-C39 = CMP-0006214-2: CAP, CERM, 47 pF, 50 V, +/- 5%, C0G/NP0, 0402; Manufacturer: Wurth Elektronik; TaMin_C: -55°C; Polarized: N; SizeAreaWB_mm2: 3; Value1: Unknown; U/M: EA; Value: 47pF; TaMax_C: 125°C; SizeZ_mm: 0.6; SizeX_mm: 1; SizeY_mm: 0.5; Cap_Case: 0402; CompType: Capacitor; AEC Category: Q200
C45 = CMP-0006217-2: CAP, CERM, 100 pF, 50 V, +/- 5%, C0G/NP0, 0402; Manufacturer: Wurth Elektronik; TaMin_C: -55°C; Polarized: N; SizeAreaWB_mm2: 3; Value1: Unknown; U/M: EA; Value: 100pF; TaMax_C: 125°C; SizeZ_mm: 0.6; SizeX_mm: 1; SizeY_mm: 0.5; AEC Category: Q200
C47 = CMP-0007468-5: CAP, CERM, 0.01 uF, 100 V, +/- 10%, X7R, 0603; Manufacturer: MuRata; TaMin_C: -55°C; Polarized: N; SizeAreaWB_mm2: 4.68; Value1: Unknown; U/M: EA; Value: 0.01uF; TaMax_C: 125°C; SizeZ_mm: 1; SizeX_mm: 1.6; SizeY_mm: 0.8; SizeArea_mm2: 1.28; Cap_F: 10nF; AEC Category: Q200
C48 = CMP-0007207-4: CAP, CERM, 3000 pF, 50 V, +/- 5%, C0G/NP0, 0603; Manufacturer: MuRata; TaMin_C: -55°C; Polarized: N; SizeAreaWB_mm2: 4.68; Value1: Unknown; U/M: EA; Value: 3000pF; TaMax_C: 125°C; SizeZ_mm: 1; SizeX_mm: 1.6; SizeY_mm: 0.8; SizeArea_mm2: 1.28; Cap_F: 3nF; AEC Category: Q200
C49 = CMP-0007877-2: CAP, CERM, 2.2 uF, 50 V, +/- 10%, X7R, 0805; Manufacturer: TDK; TaMin_C: -55°C; ESR_ohm: 3.66m; Polarized: N; SizeAreaWB_mm2: 6.75; Value1: 0.00366 ohm; U/M: EA; Value: 2.2uF; TaMax_C: 125°C; SizeZ_mm: 1.45; SizeX_mm: 2; SizeY_mm: 1.25; Cap_Case: 0805; SizeArea_mm2: 2.5; Cap_F: 2.2µF; IRMS_A: 3.41207A; AEC Category: Q200
C50 C52 = CMP-0008725-2: CAP, CERM, 3.3 uF, 100 V, +/- 20%, X7S, 1206_190; PartNumber: C3216X7S2A335M160AB; Manufacturer: TDK; Polarized: N; Value: 3.3uF; U/M: EA; Cap_F: 3.3µF; ESR_ohm: 3.048m; Value1: 0.003048 ohm; IRMS_A: 4.15703A; TaMin_C: -55°C; TaMax_C: 125°C; SizeArea_mm2: 5.12; SizeAreaWB_mm2: 10.92; SizeX_mm: 3.2; SizeY_mm: 1.6; SizeZ_mm: 1.9; AEC Category: Q200
C53 = CMP-0007469-4: CAP, CERM, 0.1 uF, 100 V, +/- 10%, X7R, 0603; PartNumber: GRM188R72A104KA35D; Manufacturer: MuRata; Polarized: N; Value: 0.1uF; U/M: EA; Cap_F: 100nF; Value1: Unknown; TaMin_C: -55°C; TaMax_C: 125°C; SizeArea_mm2: 1.28; SizeAreaWB_mm2: 4.68; SizeX_mm: 1.6; SizeY_mm: 0.8; SizeZ_mm: 1; AEC Category: Q200
C54 = CMP-0007508-5: CAP, CERM, 1 uF, 50 V, +/- 10%, X7R, 0603; Manufacturer: Taiyo Yuden; TaMin_C: -55°C; Polarized: N; SizeAreaWB_mm2: 4.68; Value1: Unknown; U/M: EA; Value: 1uF; TaMax_C: 125°C; SizeZ_mm: 1; SizeX_mm: 1.6; SizeY_mm: 0.8; SizeArea_mm2: 1.28; Cap_F: 1µF; AEC Category: Q200
C55 = CMP-0006228-2: as C1 on sheet TIDA-01629_CurrentSense
C56 = CMP-0007691-2: CAP, CERM, 10 uF, 10 V, +/- 10%, X7R, 0805; Manufacturer: Wurth Elektronik; TaMin_C: -55°C; Polarized: N; SizeAreaWB_mm2: 6.75; Value1: Unknown; U/M: EA; Value: 10uF; TaMax_C: 125°C; SizeZ_mm: 1.45; SizeX_mm: 2; SizeY_mm: 1.25; Cap_Case: 0805; SizeArea_mm2: 2.5; Cap_F: 10µF; AEC Category: Q200
C57 = CMP-0007007-5: CAP, CERM, 10 uF, 25 V, +/- 20%, X5R, 0603; PartNumber: C1608X5R1E106M080AC; Manufacturer: TDK; Polarized: N; Value: 10uF; U/M: EA; Cap_F: 10µF; ESR_ohm: 4.639m; Value1: 0.004639 ohm; IRMS_A: 2.41407A; TaMin_C: -55°C; TaMax_C: 85°C; Cap_Case: 0603; SizeArea_mm2: 1.28; SizeAreaWB_mm2: 4.68; SizeX_mm: 1.6; SizeY_mm: 0.8; SizeZ_mm: 1; AEC Category: Q200
C58 = CMP-0007158-5: CAP, CERM, 22 uF, 10 V, +/- 20%, X5R, 0603; PartNumber: GRM187R61A226ME15D; Manufacturer: MuRata; Polarized: N; Value: 22uF; U/M: EA; Cap_F: 22µF; Value1: Unknown; TaMin_C: -55°C; TaMax_C: 85°C; Cap_Case: 0603; SizeArea_mm2: 1.28; SizeAreaWB_mm2: 4.68; SizeX_mm: 1.6; SizeY_mm: 0.8; SizeZ_mm: 1; AEC Category: Q200
C74-C79 = CMP-0007159-4: CAP, CERM, 1000 pF, 25 V, +/- 5%, C0G/NP0, 0603; Manufacturer: MuRata; TaMin_C: -55°C; Polarized: N; SizeAreaWB_mm2: 4.68; Value1: Unknown; U/M: EA; Value: 1000pF; TaMax_C: 125°C; SizeZ_mm: 1; SizeX_mm: 1.6; SizeY_mm: 0.8; SizeArea_mm2: 1.28; Cap_F: 1nF; AEC Category: Q200
D1 D2 = CMP-0028517-1: Diode, Schottky, 200 V, 1 A, PowerDI123; Manufacturer: Diodes Inc.; Io_A: 1A; Green_Lifecycle: Active; SizeAreaWB_mm2: 13.066; Vr_V: 200V; Green_REACh: Passed; TJmax_C: 175°C; U/M: EA; Value: 200V; SizeZ_mm: 0.98; SizeX_mm: 3.7; SizeY_mm: 1.78; Vf_V: 8.5dV; Value2: 0.85V; SizeArea_mm2: 6.586; AEC Category: Q101; RJC_CperW: 7
D3 D4 = CMP-0002905-1: LED, Green, SMD; Manufacturer: Wurth Elektronik; PartNumber: 150060GS75000; Type: InGaN; Vf_V: 3.2V; Io_A: 20mA; Tjmax_C: 85°C; Value1: W; Angle: 140; U/M: EA
J1 = CMP-0054787-1: Header, 2.54mm, 2x1, Gold, SMT; Manufacturer: Wurth Elektronik; CNHeader: TRUE; Shrouded: N; Gender: Male; Row_Count: 1; Pitch_mm: 2.54; CT: FALSE
L1 L6 = CMP-0003183-2: Ferrite Bead, 100 ohm @ 100 MHz, 0.5 A, 0603; Manufacturer: Wurth Elektronik; Ztyp@1GHz_Ohm: 137.267; ZTyp@100MHz_Ohm: 100; SizeAreaWB_mm2: 4.68; DCR_ohm: 1.5d; Value1: 0.15 ohm; Value: 100 ohm; Imax_A: 5dA; SizeZ_mm: 1; SizeX_mm: 1.6; SizeY_mm: 0.8; Value2: 0.5A; SizeArea_mm2: 1.28
L2 = CMP-0077440-1: Inductor, Shielded, Ferrite, 220 µH, .5 A, .624 ohm, SMD; Manufacturer: Coilcraft; SizeAreaWB_mm2: 81; Irms: 0.55A @ 20C rise; SizeArea_mm2: 49; AEC Qualified: N; AEC Category: Q200; Value: 220uH; SizeZ_mm: 4.8; Imax_A: 5dA; SizeY_mm: 7; Value2: .5A; Isat: .5A @ 10% inductance drop; DCR_ohm: 6.24d
L3 = CMP-0062507-2: Inductor, Shielded, Ferrite, 33 uH, 0.085 A, 1.4 ohm, SMD; PartNumber: NLFV25T-330K-PF; Manufacturer: TDK; Value: 33uH; Ind_H: 33µH; Imax_A: 85mA; Irms: 0.085A @ 20C rise; Isat: 0.085A @ 10% inductance drop; DCR_ohm: 1.4; Value1: 1.4 ohm; Value2: 0.085A; AEC Category: Q200; Green_Lifecycle: Active; Green_REACh: Passed; SizeArea_mm2: 4.5; SizeAreaWB_mm2: 9.8; SizeX_mm: 2.5; SizeY_mm: 1.8; SizeZ_mm: 2
L4 = CMP-0003215-1: Ferrite Bead, 100 ohm @ 100 MHz, 0.2 A, 0402; Manufacturer: Wurth Elektronik; Ztyp@1GHz_Ohm: 190.588; ZTyp@100MHz_Ohm: 100; SizeAreaWB_mm2: 3; DCR_ohm: 3d; Value1: 0.3 ohm; Value: 100 ohm; Imax_A: 2dA; SizeZ_mm: 0.6; SizeX_mm: 1; SizeY_mm: 0.5; Value2: 0.2A
L5 = CMP-0061137-1: Inductor, Shielded, Composite, 2.2 uH, 1.6 A, 0.08 ohm, SMD; PartNumber: XFL3012-222MEB; Manufacturer: Coilcraft; Value: 2.2uH; Ind_H: 2.2µH; Imax_A: 1.6A; Irms: 1.9A @ 40C rise; Isat: 1.6A @ 30% inductance drop; DCR_ohm: 0.08; SizeAreaWB_mm2: 16; SizeArea_mm2: 9; SizeX_mm: 3; SizeZ_mm: 1.2; AEC Category: Q200; Green_Lifecycle: Not Set; Green_REACh: Incomplete
NT1-NT7 = CMP-0078142-1: Single point connection between nets.
Q1-Q6 = CMP-0000958-2: MOSFET, N-CH, 100 V, 17 A, DNK0008A (VSON-CLIP-8); Alternate Manufacturer: None; Manufacturer: Texas Instruments; SizeZ_mm: 1; ChType: N; Value2: 48 nC; VdsMax_V: 100V; SizeX_mm: 6; SizeY_mm: 5; Vgs_V: 20V; QgTyp_nC: 48; Value: 100V; SizeArea_mm2: 30; AEC Category: Q101; IdsMax_A: 17A; SizeAreaWB_mm2: 56; U/M: EA
R19 = CMP-0026050-3: RES, 17.4 k, 1%, 0.063 W, AEC-Q200 Grade 0, 0402; Manufacturer: Vishay-Dale; Power_W: 63mW; TempCo: 100 ppm/C; Value_Code: 17k4; Value: 17.4k; EIA_Code: E96; SizeX_mm: 1; SizeY_mm: 0.5; SizeZ_mm: 0.6; Value2: 0.063W; AEC Qualified: Y; VDC_V: 50V; AEC Category: Q200; AEC Grade: 0
R20 R22 R23 R32 R33 R36 = CMP-0020521-2: RES, 2.7, 5%, 0.125 W, 0805; Manufacturer: Vishay-Dale; Power_W: 125mW; TempCo: 200 ppm/C; Value_Code: 2R70; U/M: EA; Value: 2.7; EIA_Code: E24; SizeX_mm: 2; SizeY_mm: 1.25; SizeZ_mm: 1.45; Value2: 0.125W; SizeArea_mm2: 2.5; CompType: Resistor; VDC_V: 150V; AEC Category: Q200
R21 = CMP-0025950-3: as R1 on sheet TIDA-01629_CurrentSense
R24-R29 = CMP-0026164-2: RES, 20.0, 1%, 0.063 W, AEC-Q200 Grade 0, 0402; Manufacturer: Vishay-Dale; Power_W: 63mW; TempCo: 100 ppm/C; Value_Code: 20R0; Value: 20.0; EIA_Code: E96; Res_ohm: 20; SizeX_mm: 1; SizeY_mm: 0.5; SizeZ_mm: 0.6; Value2: 0.063W; CompType: Resistor; AEC Qualified: Y; VDC_V: 50V; AEC Category: Q200; AEC Grade: 0
R30 = CMP-0026852-2: RES, 1.0 k, 5%, 0.063 W, 0402; Manufacturer: Vishay-Dale; Power_W: 63mW; TempCo: 200 ppm/C; Value_Code: 1k00; U/M: EA; Value: 1.0k; EIA_Code: E24; Res_ohm: 1k; SizeX_mm: 1; SizeY_mm: 0.5; SizeZ_mm: 0.6; Value2: 0.063W; VDC_V: 50V; AEC Category: Q200
R31 = CMP-0026880-3: RES, 22, 5%, 0.063 W, AEC-Q200 Grade 0, 0402; Manufacturer: Vishay-Dale; Power_W: 63mW; TempCo: 200 ppm/C; Value_Code: 22R0; Value: 22; EIA_Code: E24; SizeX_mm: 1; SizeY_mm: 0.5; SizeZ_mm: 0.6; Value2: 0.063W; AEC Qualified: Y; VDC_V: 50V; AEC Category: Q200; AEC Grade: 0
R34 = CMP-0026404-2: RES, 49.9, 1%, 0.063 W, AEC-Q200 Grade 0, 0402; Manufacturer: Vishay-Dale; Power_W: 63mW; TempCo: 100 ppm/C; Value_Code: 49R9; Value: 49.9; EIA_Code: E96; SizeX_mm: 1; SizeY_mm: 0.5; SizeZ_mm: 0.6; Value2: 0.063W; AEC Qualified: Y; VDC_V: 50V; AEC Category: Q200; AEC Grade: 0
R35 = CMP-0026825-4: RES, 10 k, 5%, 0.063 W, 0402; Manufacturer: Vishay-Dale; Power_W: 63mW; TempCo: 200 ppm/C; Value_Code: 10k0; U/M: EA; Value: 10k; EIA_Code: E24; SizeX_mm: 1; SizeY_mm: 0.5; SizeZ_mm: 0.6; Value2: 0.063W; VDC_V: 50V; AEC Category: Q200
R37 = CMP-0020442-2: RES, 0, 5%, 0.125 W, 0805; Manufacturer: Vishay-Dale; Power_W: 125mW; TempCo: 200 ppm/C; Value_Code: 0000; U/M: EA; Value: 0; EIA_Code: E24; SizeX_mm: 2; SizeY_mm: 1.25; SizeZ_mm: 1.45; Value2: 0.125W; SizeArea_mm2: 2.5; VDC_V: 150V; AEC Category: Q200
R38 = CMP-0026162-2: RES, 20.0 k, 1%, 0.063 W, AEC-Q200 Grade 0, 0402; Manufacturer: Vishay-Dale; Power_W: 63mW; TempCo: 100 ppm/C; Value_Code: 20k0; Value: 20.0k; EIA_Code: E96; Res_ohm: 20k; SizeX_mm: 1; SizeY_mm: 0.5; SizeZ_mm: 0.6; Value2: 0.063W; AEC Qualified: Y; VDC_V: 50V; AEC Category: Q200; AEC Grade: 0
R39 = CMP-0026879-3: RES, 22 k, 5%, 0.063 W, AEC-Q200 Grade 0, 0402; Manufacturer: Vishay-Dale; Power_W: 63mW; TempCo: 200 ppm/C; Value_Code: 22k0; Value: 22k; EIA_Code: E24; SizeX_mm: 1; SizeY_mm: 0.5; SizeZ_mm: 0.6; Value2: 0.063W; AEC Qualified: Y; VDC_V: 50V; AEC Category: Q200; AEC Grade: 0
R40 = CMP-0026646-1: RES, 0.91, 1%, 0.125 W, 0402; Manufacturer: Panasonic; Power_W: 125mW; TempCo: 250 ppm/C; Value_Code: R910; U/M: EA; Value: 0.91; EIA_Code: E96; Res_ohm: 9.1d; SizeX_mm: 1; SizeY_mm: 0.5; SizeZ_mm: 0.6; Value2: 0.125W; AEC Category: Q200
R41 = CMP-0026280-2: RES, 301 k, 1%, 0.063 W, AEC-Q200 Grade 0, 0402; Manufacturer: Vishay-Dale; Power_W: 63mW; TempCo: 100 ppm/C; Value: 301k; EIA_Code: E96; SizeX_mm: 1; SizeY_mm: 0.5; SizeZ_mm: 0.6; Value2: 0.063W; AEC Qualified: Y; VDC_V: 50V; AEC Category: Q200; AEC Grade: 0
R42 = CMP-0025956-2: RES, 107 k, 1%, 0.063 W, 0402; Manufacturer: Vishay-Dale; Power_W: 63mW; TempCo: 100 ppm/C; U/M: EA; Value: 107k; EIA_Code: E96; SizeX_mm: 1; SizeY_mm: 0.5; SizeZ_mm: 0.6; Value2: 0.063W; VDC_V: 50V; AEC Category: Q200
R43 = CMP-0026405-2: RES, 4.02 k, 1%, 0.063 W, AEC-Q200 Grade 0, 0402; Manufacturer: Vishay-Dale; Power_W: 63mW; TempCo: 100 ppm/C; Value_Code: 4k02; Value: 4.02k; EIA_Code: E96; SizeX_mm: 1; SizeY_mm: 0.5; SizeZ_mm: 0.6; Value2: 0.063W; AEC Qualified: Y; VDC_V: 50V; AEC Category: Q200; AEC Grade: 0
R44 = CMP-0026856-5: RES, 1.5 k, 5%, 0.063 W, AEC-Q200 Grade 0, 0402; Manufacturer: Vishay-Dale; Power_W: 63mW; TempCo: 200 ppm/C; Value_Code: 1k50; Value: 1.5k; EIA_Code: E24; SizeX_mm: 1; SizeY_mm: 0.5; SizeZ_mm: 0.6; Value2: 0.063W; AEC Qualified: Y; VDC_V: 50V; AEC Category: Q200; AEC Grade: 0
TP1 = CMP-0055138-1: Test Point, Miniature, Black, TH; Manufacturer: Keystone; CNHeader: FALSE; Green_Lifecycle: Active; Green_REACh: Passed; ContactFinish: Silver; CT: TRUE
TP2-TP7 = CMP-0003825-1: 1mm Test Point, SMT; Manufacturer: Any
U6 = CMP-0013783-2: 100-V Three-Phase Smart Gate Driver, RGZ0048L (VQFN-48); Manufacturer: Texas Instruments; Alternate PartNumber: DRV8350RSRGZT; SizeX_mm: 7; CompType: IC; SizeZ_mm: 1; SizeArea_mm2: 49; SizeAreaWB_mm2: 81; U/M: EA
U7 = CMP-0037789-2: Buck Step Down Regulator with 3 to 17 V Input and 3.3 V Output, -40 to 85 degC, 8-Pin WSON (DSG), Green (RoHS & no Sb/Br); Manufacturer: Texas Instruments; Duty Cycle(Max)(%): 100; Iout(Max)(A): 1; Iq(Typ)(mA): 0.017; Preset Vout(V): 3.3; Rating: Catalog; SubFamily: Step-Down Regulator; Switch Current Limit(Typ)(A): 1.8; Synchronous Rectification: TRUE; Vin(Max)(V): 17; Vin(Min)(V): 3

## Sheet TIDA-01629_Interface.SchDoc
size 431 x 279 mm; Date: Not shown in title block; ApprovedBy: Not shown in title block; CheckedBy: Not shown in title block; Author: Not shown in title block; CompanyName: Not shown in title block; Engineer: Not shown in title block; Organization: Not shown in title block; Address1: Not shown in title block; Address2: Not shown in title block; Address3: Not shown in title block; Address4: Not shown in title block; DocumentNumber: 1; Revision: Use project parameter SCH_Rev; SheetNumber: 2; SheetTotal: 3; PageSetup: Record=PageOptions¦CenterHorizontal=True¦CenterVertical=True¦PrintScale=1.00¦XCorrection=1.00¦YCorrection=1.00¦PrintKind=0¦BorderSize=5000000¦LeftOffset=0¦BottomOffset=0¦Orientation=2¦PaperLength=1000¦PaperWidth=1000¦Scale=100¦PaperSource=15¦PrintQuality=600¦MediaType=1¦DitherType=10¦PaperKind=Letter¦PrintScaleMode=1
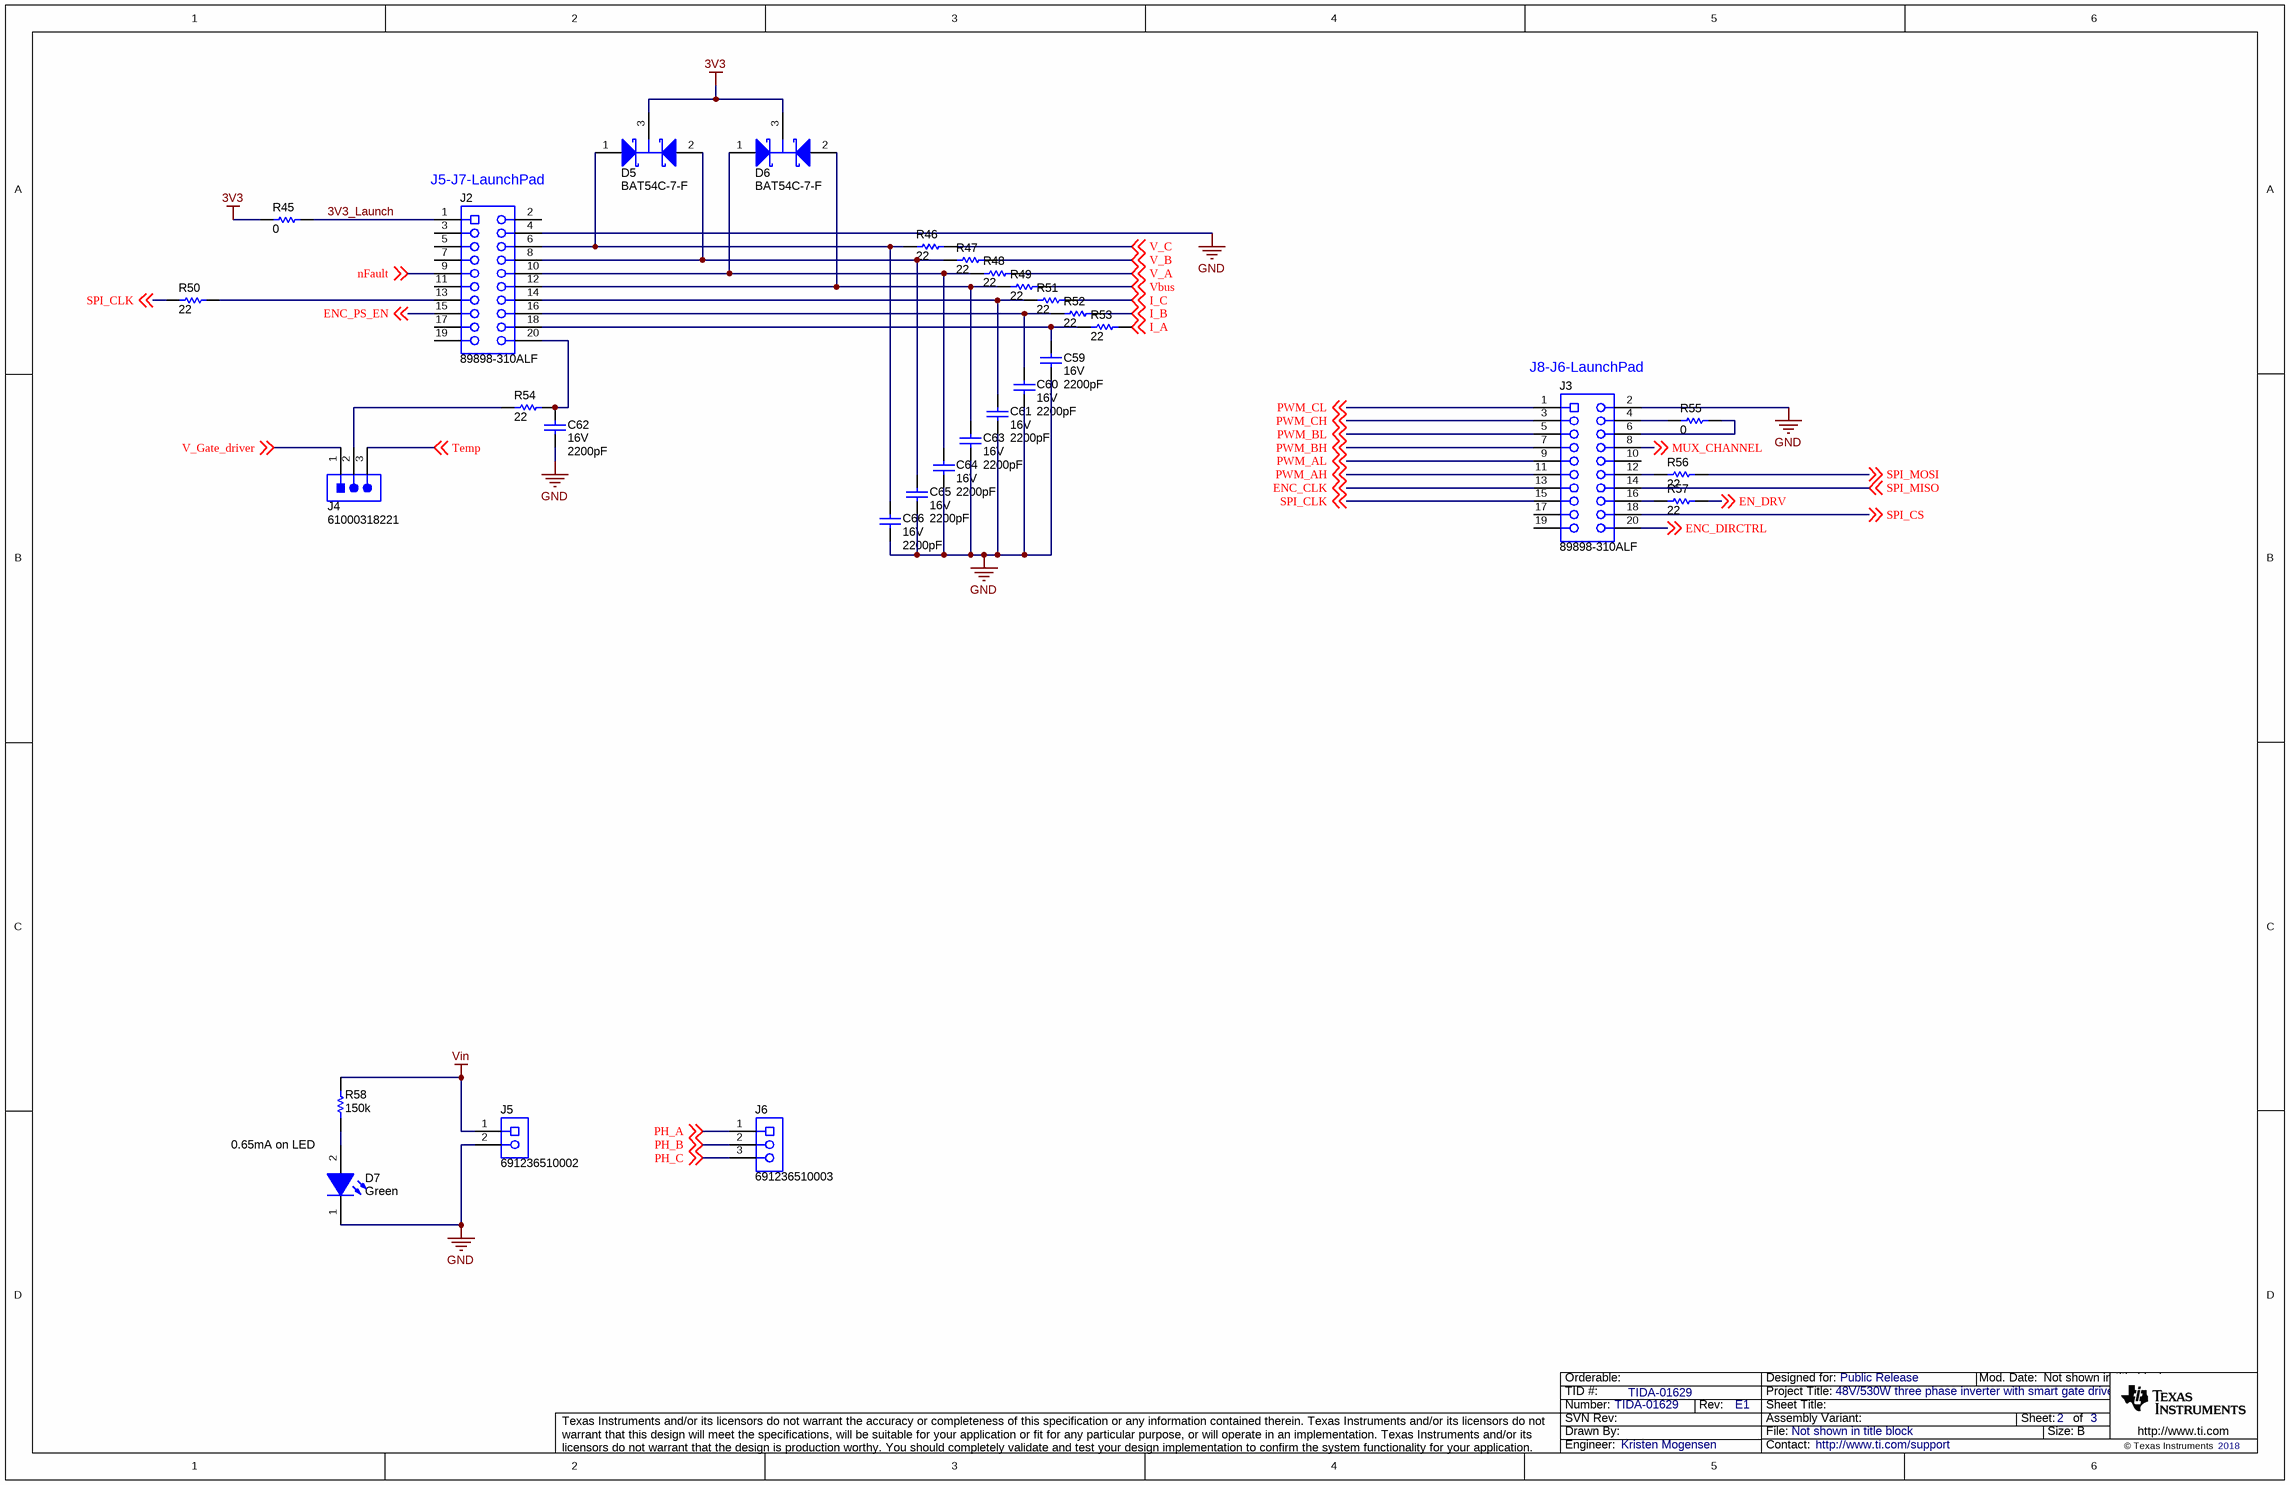
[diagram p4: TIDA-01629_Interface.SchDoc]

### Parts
C59  VDC_V: 16V  ValueDisplayed: 2200pF  [0402]  (hidden comment: GRM155R71C222KA01D)
C60  VDC_V: 16V  ValueDisplayed: 2200pF  [0402]  (hidden comment: GRM155R71C222KA01D)
C61  VDC_V: 16V  ValueDisplayed: 2200pF  [0402]  (hidden comment: GRM155R71C222KA01D)
C62  VDC_V: 16V  ValueDisplayed: 2200pF  [0402]  (hidden comment: GRM155R71C222KA01D)
C63  VDC_V: 16V  ValueDisplayed: 2200pF  [0402]  (hidden comment: GRM155R71C222KA01D)
C64  VDC_V: 16V  ValueDisplayed: 2200pF  [0402]  (hidden comment: GRM155R71C222KA01D)
C65  VDC_V: 16V  ValueDisplayed: 2200pF  [0402]  (hidden comment: GRM155R71C222KA01D)
C66  VDC_V: 16V  ValueDisplayed: 2200pF  [0402]  (hidden comment: GRM155R71C222KA01D)
D5  BAT54C-7-F  [SOT-23]
D6  BAT54C-7-F  [SOT-23]
D7  value Green  [WL-SMCW_GREEN]  (hidden comment: LED_A2_K1)
J2  89898-310ALF  [FCI_89898-310ALF]
J3  89898-310ALF  [FCI_89898-310ALF]
J4  61000318221  [Wurth_61000318221]
J5  691236510002  [Wurth_691236510002]
J6  691236510003  [Wurth_691236510003]
R45  ValueDisplayed: 0  [0805_HV]  (hidden comment: CRCW08050000Z0EA)
R46  ValueDisplayed: 22  [0402]  (hidden comment: CRCW040222R0JNED)
R47  ValueDisplayed: 22  [0402]  (hidden comment: CRCW040222R0JNED)
R48  ValueDisplayed: 22  [0402]  (hidden comment: CRCW040222R0JNED)
R49  ValueDisplayed: 22  [0402]  (hidden comment: CRCW040222R0JNED)
R50  ValueDisplayed: 22  [0603]  (hidden comment: CRCW060322R0JNEA)
R51  ValueDisplayed: 22  [0402]  (hidden comment: CRCW040222R0JNED)
R52  ValueDisplayed: 22  [0402]  (hidden comment: CRCW040222R0JNED)
R53  ValueDisplayed: 22  [0402]  (hidden comment: CRCW040222R0JNED)
R54  ValueDisplayed: 22  [0603]  (hidden comment: CRCW060322R0JNEA)
R55  ValueDisplayed: 0  [0402]  (hidden comment: RC0402JR-070RL)
R56  ValueDisplayed: 22  [0402S]  (hidden comment: CRCW040222R0JNED)
R57  ValueDisplayed: 22  [0402]  (hidden comment: CRCW040222R0JNED)
R58  ValueDisplayed: 150k  [0402]  (hidden comment: CRCW0402150KJNED)

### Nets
3V3: D5.3(K) D6.3(K) R45.1
GND: C59.2 C60.2 C61.2 C62.2 C63.2 C64.2 C65.2 C66.2 D7.1(K) J2.4 J3.2 J5.2
Vin: J5.1 R58.2
3V3_Launch: J2.1 R45.2
EN_DRV: R57.2 ; off-sheet EN_DRV
ENC_CLK: J3.13 ; off-sheet ENC_CLK
ENC_DIRCTRL: J3.20 ; off-sheet ENC_DIRCTRL
ENC_PS_EN: J2.15 ; off-sheet ENC_PS_EN
I_A: R53.2 ; off-sheet I_A
I_B: R52.2 ; off-sheet I_B
I_C: R51.2 ; off-sheet I_C
MUX_CHANNEL: J3.8 ; off-sheet MUX_CHANNEL
nFault: J2.9 ; off-sheet nFault
PH_A: J6.1 ; off-sheet PH_A  [project net PH_A_P]
PH_B: J6.2 ; off-sheet PH_B  [project net PH_B_P]
PH_C: J6.3 ; off-sheet PH_C  [project net PH_C_P]
PWM_AH: J3.11 ; off-sheet PWM_AH
PWM_AL: J3.9 ; off-sheet PWM_AL
PWM_BH: J3.7 ; off-sheet PWM_BH
PWM_BL: J3.5 ; off-sheet PWM_BL
PWM_CH: J3.3 ; off-sheet PWM_CH
PWM_CL: J3.1 ; off-sheet PWM_CL
SPI_CLK: J3.15 R50.1 ; off-sheet SPI_CLK
SPI_CS: J3.18 ; off-sheet SPI_CS
SPI_MISO: J3.14 ; off-sheet SPI_MISO
SPI_MOSI: R56.2 ; off-sheet SPI_MOSI
Temp: J4.3 ; off-sheet Temp
V_A: R48.2 ; off-sheet V_A
V_B: R47.2 ; off-sheet V_B
V_C: R46.2 ; off-sheet V_C
V_Gate_driver: J4.1 ; off-sheet V_Gate_driver
Vbus: R49.2 ; off-sheet Vbus
NetC59_1: C59.1 J2.18 R53.1
NetC60_1: C60.1 J2.16 R52.1
NetC61_1: C61.1 J2.14 R51.1
NetC62_1: C62.1 J2.20 R54.2
NetC63_1: C63.1 D6.2(A2) J2.12 R49.1
NetC64_1: C64.1 D6.1(A1) J2.10 R48.1
NetC65_1: C65.1 D5.2(A2) J2.8 R47.1
NetC66_1: C66.1 D5.1(A1) J2.6 R46.1
NetD7_2: D7.2(A) R58.1
NetJ2_13: J2.13 R50.2
NetJ3_4: J3.4 R55.2
NetJ3_6: J3.6 R55.1
NetJ3_12: J3.12 R56.1
NetJ3_16: J3.16 R57.1
NetJ4_2: J4.2 R54.1

Not connected (* = marked no-connect by the designer): J2 2 3 5 7 11 17 19; J3 10 17 19

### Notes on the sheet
- (near J2) J5-J7-LaunchPad
- (near J3) J8-J6-LaunchPad
- 0.65mA on LED

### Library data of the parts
C59-C66 = CMP-0006646-2: CAP, CERM, 2200 pF, 16 V, +/- 10%, X7R, 0402; Manufacturer: MuRata; TaMin_C: -55°C; Polarized: N; SizeAreaWB_mm2: 3; Value1: Unknown; U/M: EA; Value: 2200pF; TaMax_C: 125°C; SizeZ_mm: 0.6; SizeX_mm: 1; SizeY_mm: 0.5; Cap_F: 2.2nF; AEC Category: Q200
D5 D6 = CMP-0028453-1: Diode, Schottky, 30 V, 0.2 A, SOT-23; Manufacturer: Diodes Inc.; Io_A: 2dA; Green_Lifecycle: Active; SizeAreaWB_mm2: 14; Vr_V: 30V; Green_REACh: Passed; Value1: 0.2A; TJmax_C: 125°C; U/M: EA; Value: 30V; SizeZ_mm: 1.1; SizeX_mm: 2.5; SizeY_mm: 3; Vf_V: 6.5dV; Value2: 0.65V; SizeArea_mm2: 7.5; AEC Category: Q101
D7 = CMP-0002905-1: as D3 on sheet TIDA-01629_Gate_Driver
J2 J3 = CMP-0055772-1: Receptacle, 2.54mm, 10x2, Gold, SMT; Manufacturer: FCI; CNHeader: FALSE; Current_A: 3A; Gender: Female; Cert_CULUS: Y; Voltage_V: 1kV; Row_Count: 2; Pitch_mm: 2.54
J4 = CMP-0079473-1: Header, 2.54mm, 3x1, Gold, SMT; Manufacturer: Wurth Elektronik; Pitch_mm: 2.54; Gender: Male; Cert_UL: Y; Current_A: 3A; Voltage_V: 250V; Shrouded: N; Row_Count: 1
J5 = CMP-0079044-1: Terminal Block, 5.08mm, 2x1, R/A, TH; Manufacturer: Wurth Elektronik; Pitch_mm: 5.08; Cert_VDE: Y; Gender: Female; Voltage_V: 300V; Current_A: 20A; Row_Count: 1
J6 = CMP-0079043-1: Terminal Block, 5.08mm, 3x1, R/A, TH; Manufacturer: Wurth Elektronik; Pitch_mm: 5.08; Cert_VDE: Y; Gender: Female; Voltage_V: 300V; Current_A: 20A; Row_Count: 1
R45 = CMP-0020442-2: RES, 0, 5%, 0.125 W, 0805; Manufacturer: Vishay-Dale; Power_W: 125mW; TempCo: 200 ppm/C; Value_Code: 0000; U/M: EA; Value: 0; EIA_Code: E24; SizeX_mm: 2; SizeY_mm: 1.25; SizeZ_mm: 1.45; Value2: 0.125W; SizeArea_mm2: 2.5; CompType: Resistor; VDC_V: 150V; AEC Category: Q200
R46-R49 R51-R53 R57 = CMP-0026880-3: as R31 on sheet TIDA-01629_Gate_Driver
R50 R54 = CMP-0025758-3: RES, 22, 5%, 0.1 W, 0603; Manufacturer: Vishay-Dale; Power_W: 100mW; TempCo: 200 ppm/C; Value_Code: 22R0; U/M: EA; Value: 22; EIA_Code: E24; SizeX_mm: 1.6; SizeY_mm: 0.8; SizeZ_mm: 1; Value2: 0.1W; SizeArea_mm2: 1.28; VDC_V: 75V; AEC Category: Q200
R55 = CMP-0027004-2: RES, 0, 5%, 0.063 W, 0402; Manufacturer: Yageo America; Power_W: 63mW; TempCo: 200 ppm/C; Value_Code: 0000; U/M: EA; Value: 0; EIA_Code: E24; SizeX_mm: 1; SizeY_mm: 0.5; SizeZ_mm: 0.6; Value2: 0.063W; VDC_V: 50V; AEC Category: Q200
R56 = CMP-0026880-3: RES, 22, 5%, 0.063 W, AEC-Q200 Grade 0, 0402; Manufacturer: Vishay-Dale; Power_W: 63mW; TempCo: 200 ppm/C; Value_Code: 22R0; Value: 22; EIA_Code: E24; SizeX_mm: 1; SizeY_mm: 0.5; SizeZ_mm: 0.6; Value2: 0.063W; CompType: Resistor; AEC Qualified: Y; VDC_V: 50V; AEC Category: Q200; AEC Grade: 0
R58 = CMP-0026840-2: RES, 150 k, 5%, 0.063 W, AEC-Q200 Grade 0, 0402; Manufacturer: Vishay-Dale; Power_W: 63mW; TempCo: 200 ppm/C; Value: 150k; EIA_Code: E24; SizeX_mm: 1; SizeY_mm: 0.5; SizeZ_mm: 0.6; Value2: 0.063W; AEC Qualified: Y; VDC_V: 50V; AEC Category: Q200; AEC Grade: 0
